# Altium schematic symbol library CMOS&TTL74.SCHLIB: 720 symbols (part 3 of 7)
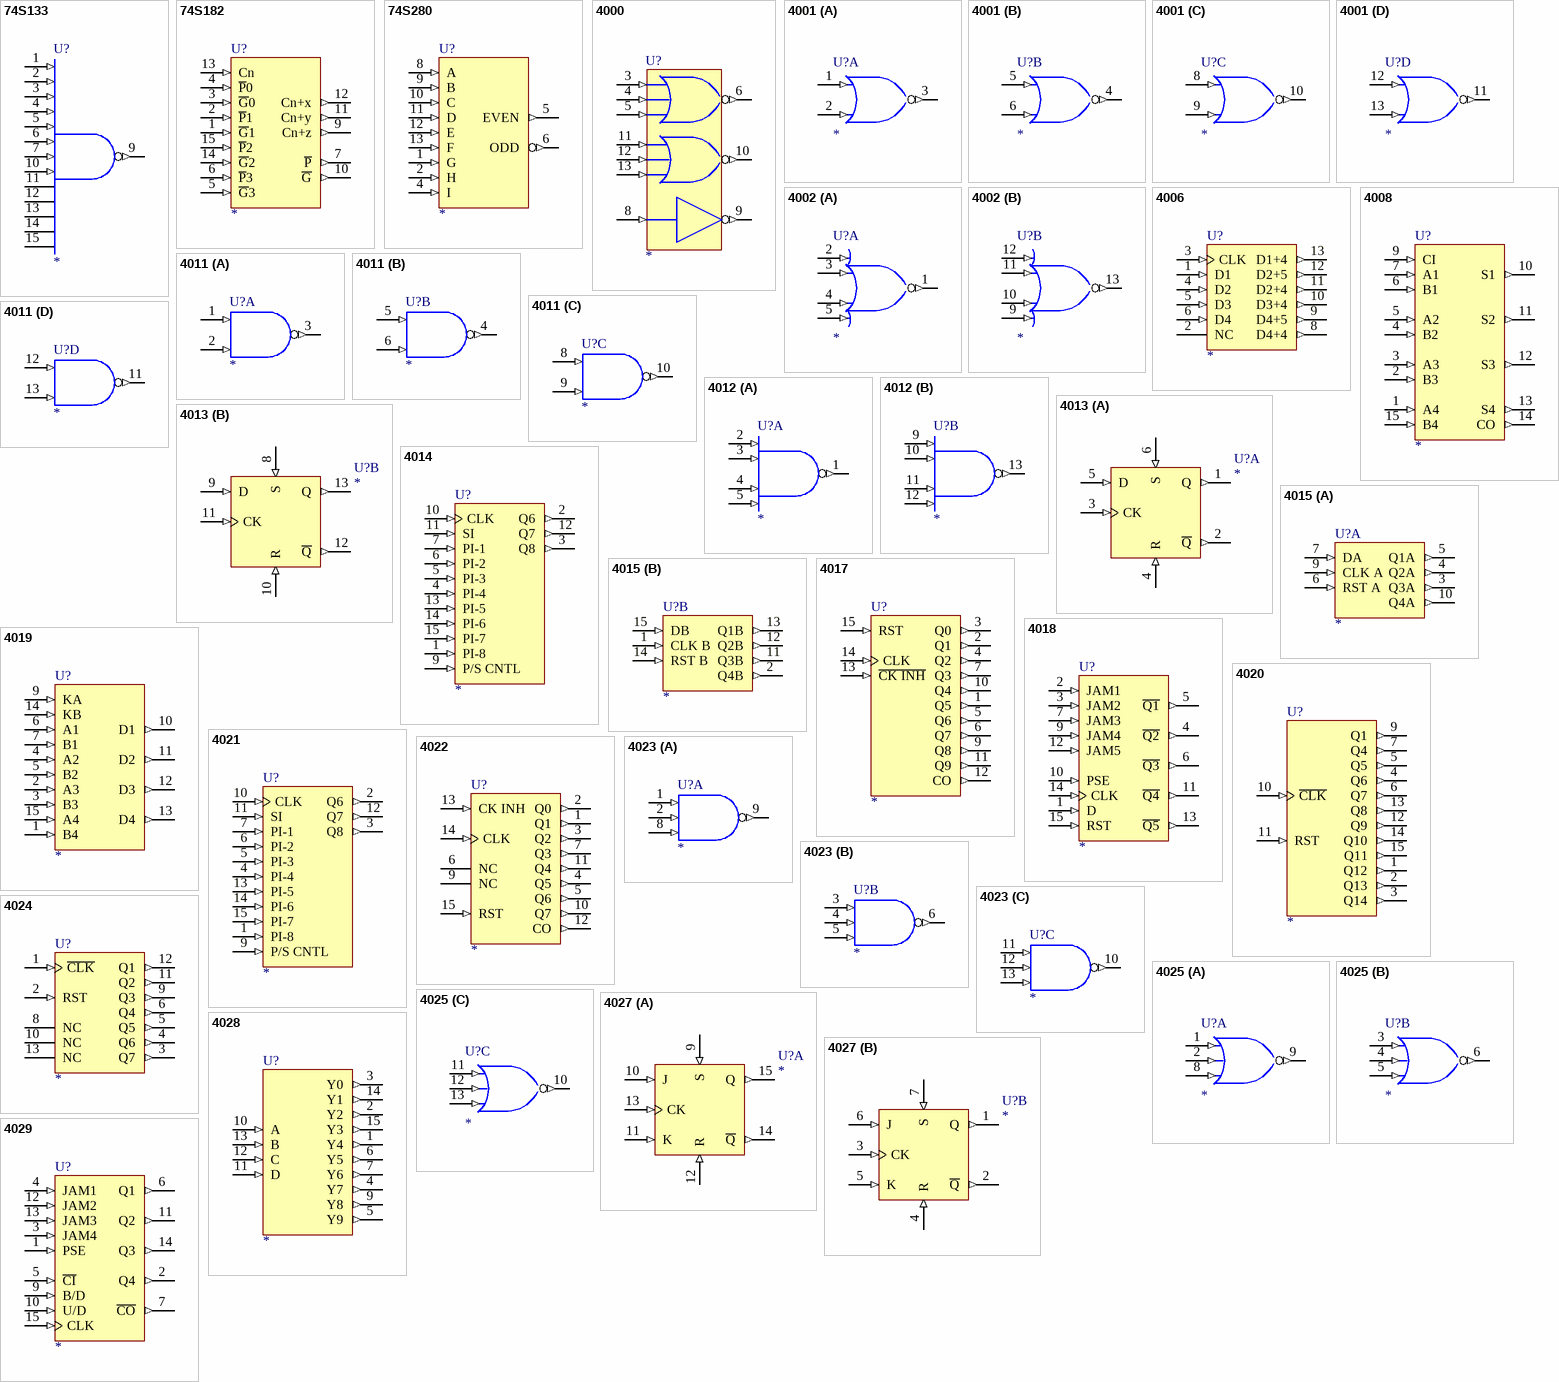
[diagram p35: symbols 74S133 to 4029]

## 4019
designator U?
Quad AND/OR Select Gate
footprint DIP-16
simulation model 4019 (SIMCODE)
pins: 1 B4 (in), 2 A3 (in), 3 B3 (in), 4 A2 (in), 5 B2 (in), 6 A1 (in), 7 B1 (in), 8 GND (power) hidden to GND, 9 KA (in), 10 D1 (out), 11 D2 (out), 12 D3 (out), 13 D4 (out), 14 KB (in), 15 A4 (in), 16 VDD (power) hidden to VDD

## 4020
designator U?
14-Stage Ripple-Carry Binary Counter
footprint DIP-16
simulation model 4020 (SIMCODE)
pins: 1 Q12 (out), 2 Q13 (out), 3 Q14 (out), 4 Q6 (out), 5 Q5 (out), 6 Q7 (out), 7 Q4 (out), 8 GND (power) hidden to GND, 9 Q1 (out), 10 ~{CLK} (in), 11 RST (in), 12 Q9 (out), 13 Q8 (out), 14 Q10 (out), 15 Q11 (out), 16 VDD (power) hidden to VDD
1 alternate drawing of the same symbol

## 4021
designator U?
8-Stage Shift Register (Asynchronous Parallel Input or Synchronous Serial Input/Serial Output)
footprint DIP-16
simulation model 4021 (SIMCODE)
pins: 1 PI-8 (in), 2 Q6 (out), 3 Q8 (out), 4 PI-4 (in), 5 PI-3 (in), 6 PI-2 (in), 7 PI-1 (in), 8 GND (power) hidden to GND, 9 P/S CNTL (in), 10 CLK (in), 11 SI (in), 12 Q7 (out), 13 PI-5 (in), 14 PI-6 (in), 15 PI-7 (in), 16 VDD (power) hidden to VDD

## 4022
designator U?
Octal Counter with 8 Decoded Outputs
footprint DIP-16
simulation model 4022 (SIMCODE)
pins: 1 Q1 (out), 2 Q0 (out), 3 Q2 (out), 4 Q5 (out), 5 Q6 (out), 6 NC, 7 Q3 (out), 8 GND (power) hidden to GND, 9 NC, 10 Q7 (out), 11 Q4 (out), 12 CO (out), 13 CK INH (in), 14 CLK (in), 15 RST (in), 16 VDD (power) hidden to VDD
1 alternate drawing of the same symbol

## 4023
designator U?
Triple 3-Input NAND Gate
footprint DIP-14
simulation model 4023 (SIMCODE)
part A pins: 1 1A (in), 2 1B (in), 7 GND (power) hidden to GND, 8 1C (in), 9 1Y (out), 14 VDD (power) hidden to VDD
part B pins: 3 2A (in), 4 2B (in), 5 2C (in), 6 2Y (out), 7 GND (power) hidden to GND, 14 VDD (power) hidden to VDD
part C pins: 7 GND (power) hidden to GND, 10 3Y (out), 11 3A (in), 12 3B (in), 13 3C (in), 14 VDD (power) hidden to VDD
2 alternate drawings of the same symbol

## 4024
designator U?
7-Stage Ripple-Carry Binary Counter
footprint DIP-14
simulation model 4024 (SIMCODE)
pins: 1 ~{CLK} (in), 2 RST (in), 3 Q7 (out), 4 Q6 (out), 5 Q5 (out), 6 Q4 (out), 7 GND (power) hidden to GND, 8 NC, 9 Q3 (out), 10 NC, 11 Q2 (out), 12 Q1 (out), 13 NC, 14 VDD (power) hidden to VDD
1 alternate drawing of the same symbol

## 4025
designator U?
Triple 3-Input NOR Gate
footprint DIP-14
simulation model 4025 (SIMCODE)
part A pins: 1 A (in), 2 B (in), 7 GND (power) hidden to GND, 8 C (in), 9 J (out), 14 VDD (power) hidden to VDD
part B pins: 3 D (in), 4 E (in), 5 F (in), 6 K (out), 7 GND (power) hidden to GND, 14 VDD (power) hidden to VDD
part C pins: 7 GND (power) hidden to GND, 10 L (out), 11 I (in), 12 H (in), 13 G (in), 14 VDD (power) hidden to VDD
1 alternate drawing of the same symbol

## 4027
designator U?
Dual J-K Master-Slave Flip-Flop
footprint DIP-16
simulation model 4027 (SIMCODE)
part A pins: 8 GND (power) hidden to GND, 9 S (in), 10 J (in), 11 K (in), 12 R (in), 13 CK (in), 14 ~{Q} (out), 15 Q (out), 16 VDD (power) hidden to VDD
part B pins: 1 Q (out), 2 ~{Q} (out), 3 CK (in), 4 R (in), 5 K (in), 6 J (in), 7 S (in), 8 GND (power) hidden to GND, 16 VDD (power) hidden to VDD

## 4028
designator U?
BCD to Decimal Decoder
footprint DIP-16
simulation model 4028 (SIMCODE)
pins: 1 Y4 (out), 2 Y2 (out), 3 Y0 (out), 4 Y7 (out), 5 Y9 (out), 6 Y5 (out), 7 Y6 (out), 8 GND (power) hidden to GND, 9 Y8 (out), 10 A (in), 11 D (in), 12 C (in), 13 B (in), 14 Y1 (out), 15 Y3 (out), 16 VDD (power) hidden to VDD
1 alternate drawing of the same symbol

## 4029
designator U?
Presettable Up/Down Counter Binary or BCD Decade
footprint DIP-16
simulation model 4029 (SIMCODE)
pins: 1 PSE (in), 2 Q4 (out), 3 JAM4 (in), 4 JAM1 (in), 5 ~{CI} (in), 6 Q1 (out), 7 ~{CO} (out), 8 GND (power) hidden to GND, 9 B/D (in), 10 U/D (in), 11 Q2 (out), 12 JAM2 (in), 13 JAM3 (in), 14 Q3 (out), 15 CLK (in), 16 VDD (power) hidden to VDD

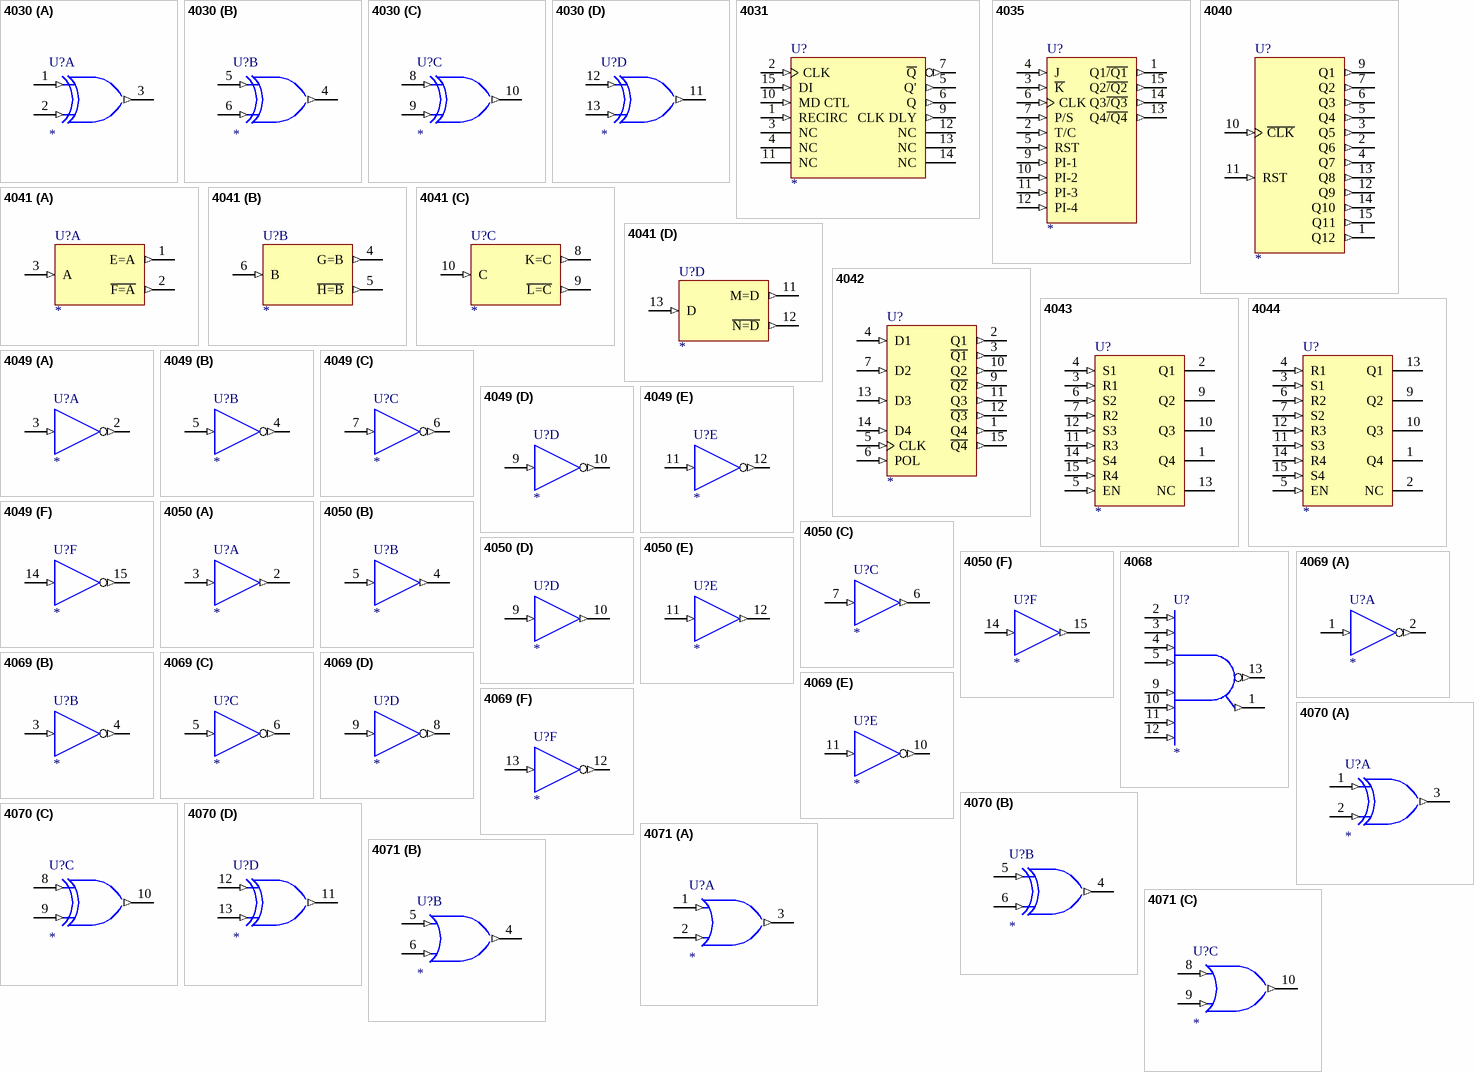
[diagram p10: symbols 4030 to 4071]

## 4030
designator U?
Quad Exclusive-OR Gate
footprint DIP-14
simulation model 4030 (SIMCODE)
part A pins: 1 1A (in), 2 1B (in), 3 1Y (out), 7 GND (power) hidden to GND, 14 VDD (power) hidden to VDD
part B pins: 4 2Y (out), 5 2A (in), 6 2B (in), 7 GND (power) hidden to GND, 14 VDD (power) hidden to VDD
part C pins: 7 GND (power) hidden to GND, 8 3A (in), 9 3B (in), 10 3Y (out), 14 VDD (power) hidden to VDD
part D pins: 7 GND (power) hidden to GND, 11 4Y (out), 12 4A (in), 13 4B (in), 14 VDD (power) hidden to VDD
1 alternate drawing of the same symbol

## 4031
designator U?
64-Stage Static Shift Register
footprint DIP-16
simulation model 4031 (SIMCODE)
pins: 1 RECIRC (in), 2 CLK (in), 3 NC, 4 NC, 5 Q' (out), 6 Q (out), 7 ~{Q} (out), 8 GND (power) hidden to GND, 9 CLK DLY (out), 10 MD CTL (in), 11 NC, 12 NC, 13 NC, 14 NC, 15 DI (in), 16 VDD (power) hidden to VDD

## 4035
designator U?
4-Stage Parallel In/Parallel Out Shift Register
footprint DIP-16
simulation model 4035 (SIMCODE)
pins: 1 Q1~{/Q1} (out), 2 T/C (in), 3 ~{K} (in), 4 J (in), 5 RST (in), 6 CLK (in), 7 P/S (in), 8 GND (power) hidden to GND, 9 PI-1 (in), 10 PI-2 (in), 11 PI-3 (in), 12 PI-4 (in), 13 Q4~{/Q4} (out), 14 Q3~{/Q3} (out), 15 Q2~{/Q2} (out), 16 VDD (power) hidden to VDD

## 4040
designator U?
12-Stage Ripple-Carry Binary Counter
footprint DIP-16
simulation model 4040 (SIMCODE)
pins: 1 Q12 (out), 2 Q6 (out), 3 Q5 (out), 4 Q7 (out), 5 Q4 (out), 6 Q3 (out), 7 Q2 (out), 8 GND (power) hidden to GND, 9 Q1 (out), 10 ~{CLK} (in), 11 RST (in), 12 Q9 (out), 13 Q8 (out), 14 Q10 (out), 15 Q11 (out), 16 VDD (power) hidden to VDD
1 alternate drawing of the same symbol

## 4041
designator U?
Quad True/Complement Buffer
footprint DIP-14
simulation model 4041 (SIMCODE)
part A pins: 1 E=A (out), 2 ~{F=A} (out), 3 A (in), 7 GND (power) hidden to GND, 14 VDD (power) hidden to VDD
part B pins: 4 G=B (out), 5 ~{H=B} (out), 6 B (in), 7 GND (power) hidden to GND, 14 VDD (power) hidden to VDD
part C pins: 7 GND (power) hidden to GND, 8 K=C (out), 9 ~{L=C} (out), 10 C (in), 14 VDD (power) hidden to VDD
part D pins: 7 GND (power) hidden to GND, 11 M=D (out), 12 ~{N=D} (out), 13 D (in), 14 VDD (power) hidden to VDD

## 4042
designator U?
Quad Clocked D-Latch
footprint DIP-16
simulation model 4042 (SIMCODE)
pins: 1 Q4 (out), 2 Q1 (out), 3 ~{Q1} (out), 4 D1 (in), 5 CLK (in), 6 POL (in), 7 D2 (in), 8 GND (power) hidden to GND, 9 ~{Q2} (out), 10 Q2 (out), 11 Q3 (out), 12 ~{Q3} (out), 13 D3 (in), 14 D4 (in), 15 ~{Q4} (out), 16 VDD (power) hidden to VDD

## 4043
designator U?
Quad 3-State R-S Latch
footprint DIP-16
simulation model 4043 (SIMCODE)
pins: 1 Q4 (hiz), 2 Q1 (hiz), 3 R1 (in), 4 S1 (in), 5 EN (in), 6 S2 (in), 7 R2 (in), 8 GND (power) hidden to GND, 9 Q2 (hiz), 10 Q3 (hiz), 11 R3 (in), 12 S3 (in), 13 NC, 14 S4 (in), 15 R4 (in), 16 VDD (power) hidden to VDD

## 4044
designator U?
Quad 3-State R-S Latch
footprint DIP-16
simulation model 4044 (SIMCODE)
pins: 1 Q4 (hiz), 2 NC, 3 S1 (in), 4 R1 (in), 5 EN (in), 6 R2 (in), 7 S2 (in), 8 GND (power) hidden to GND, 9 Q2 (hiz), 10 Q3 (hiz), 11 S3 (in), 12 R3 (in), 13 Q1 (hiz), 14 R4 (in), 15 S4 (in), 16 VDD (power) hidden to VDD

## 4049
designator U?
Inverting Hex Buffer / Converter
footprint DIP-16
simulation model 4049 (SIMCODE)
part A pins: 1 VDD (power) hidden to VDD, 2 1Y (out), 3 1A (in), 8 GND (power) hidden to GND
part B pins: 1 VDD (power) hidden to VDD, 4 2Y (out), 5 2A (in), 8 GND (power) hidden to GND
part C pins: 1 VDD (power) hidden to VDD, 6 3Y (out), 7 3A (in), 8 GND (power) hidden to GND
part D pins: 1 VDD (power) hidden to VDD, 8 GND (power) hidden to GND, 9 4A (in), 10 4Y (out)
part E pins: 1 VDD (power) hidden to VDD, 8 GND (power) hidden to GND, 11 5A (in), 12 5Y (out)
part F pins: 1 VDD (power) hidden to VDD, 8 GND (power) hidden to GND, 14 6A (in), 15 6Y (out)
2 alternate drawings of the same symbol

## 4050
designator U?
Non-Inverting Hex Buffer/Converter
footprint DIP-16
simulation model 4050 (SIMCODE)
part A pins: 1 VDD (power) hidden to VDD, 2 1Y (out), 3 1A (in), 8 GND (power) hidden to GND
part B pins: 1 VDD (power) hidden to VDD, 4 2Y (out), 5 2A (in), 8 GND (power) hidden to GND
part C pins: 1 VDD (power) hidden to VDD, 6 3Y (out), 7 3A (in), 8 GND (power) hidden to GND
part D pins: 1 VDD (power) hidden to VDD, 8 GND (power) hidden to GND, 9 4A (in), 10 4Y (out)
part E pins: 1 VDD (power) hidden to VDD, 8 GND (power) hidden to GND, 11 5A (in), 12 5Y (out)
part F pins: 1 VDD (power) hidden to VDD, 8 GND (power) hidden to GND, 14 6A (in), 15 6Y (out)
1 alternate drawing of the same symbol

## 4068
designator U?
8-Input NAND/AND Gate
footprint DIP-14
simulation model 4068 (SIMCODE)
pins: 1 Y (out), 2 A (in), 3 B (in), 4 C (in), 5 D (in), 7 GND (power) hidden to GND, 9 E (in), 10 F (in), 11 G (in), 12 H (in), 13 ~{Y} (out), 14 VDD (power) hidden to VDD

## 4069
designator U?
Hex Inverter
footprint DIP-14
simulation model 4069 (SIMCODE)
part A pins: 1 A (in), 2 Y (out), 7 GND (power) hidden to GND, 14 VDD (power) hidden to VDD
part B pins: 3 A (in), 4 Y (out), 7 GND (power) hidden to GND, 14 VDD (power) hidden to VDD
part C pins: 5 A (in), 6 Y (out), 7 GND (power) hidden to GND, 14 VDD (power) hidden to VDD
part D pins: 7 GND (power) hidden to GND, 8 Y (out), 9 A (in), 14 VDD (power) hidden to VDD
part E pins: 7 GND (power) hidden to GND, 10 Y (out), 11 A (in), 14 VDD (power) hidden to VDD
part F pins: 7 GND (power) hidden to GND, 12 Y (out), 13 A (in), 14 VDD (power) hidden to VDD

## 4070
designator U?
Quad Exclusive-OR Gate
footprint DIP-14
simulation model 4070 (SIMCODE)
part A pins: 1 1A (in), 2 1B (in), 3 1Y (out), 7 GND (power) hidden to GND, 14 VDD (power) hidden to VDD
part B pins: 4 2Y (out), 5 2A (in), 6 2B (in), 7 GND (power) hidden to GND, 14 VDD (power) hidden to VDD
part C pins: 7 GND (power) hidden to GND, 8 3A (in), 9 3B (in), 10 3Y (out), 14 VDD (power) hidden to VDD
part D pins: 7 GND (power) hidden to GND, 11 4Y (out), 12 4A (in), 13 4B (in), 14 VDD (power) hidden to VDD
1 alternate drawing of the same symbol

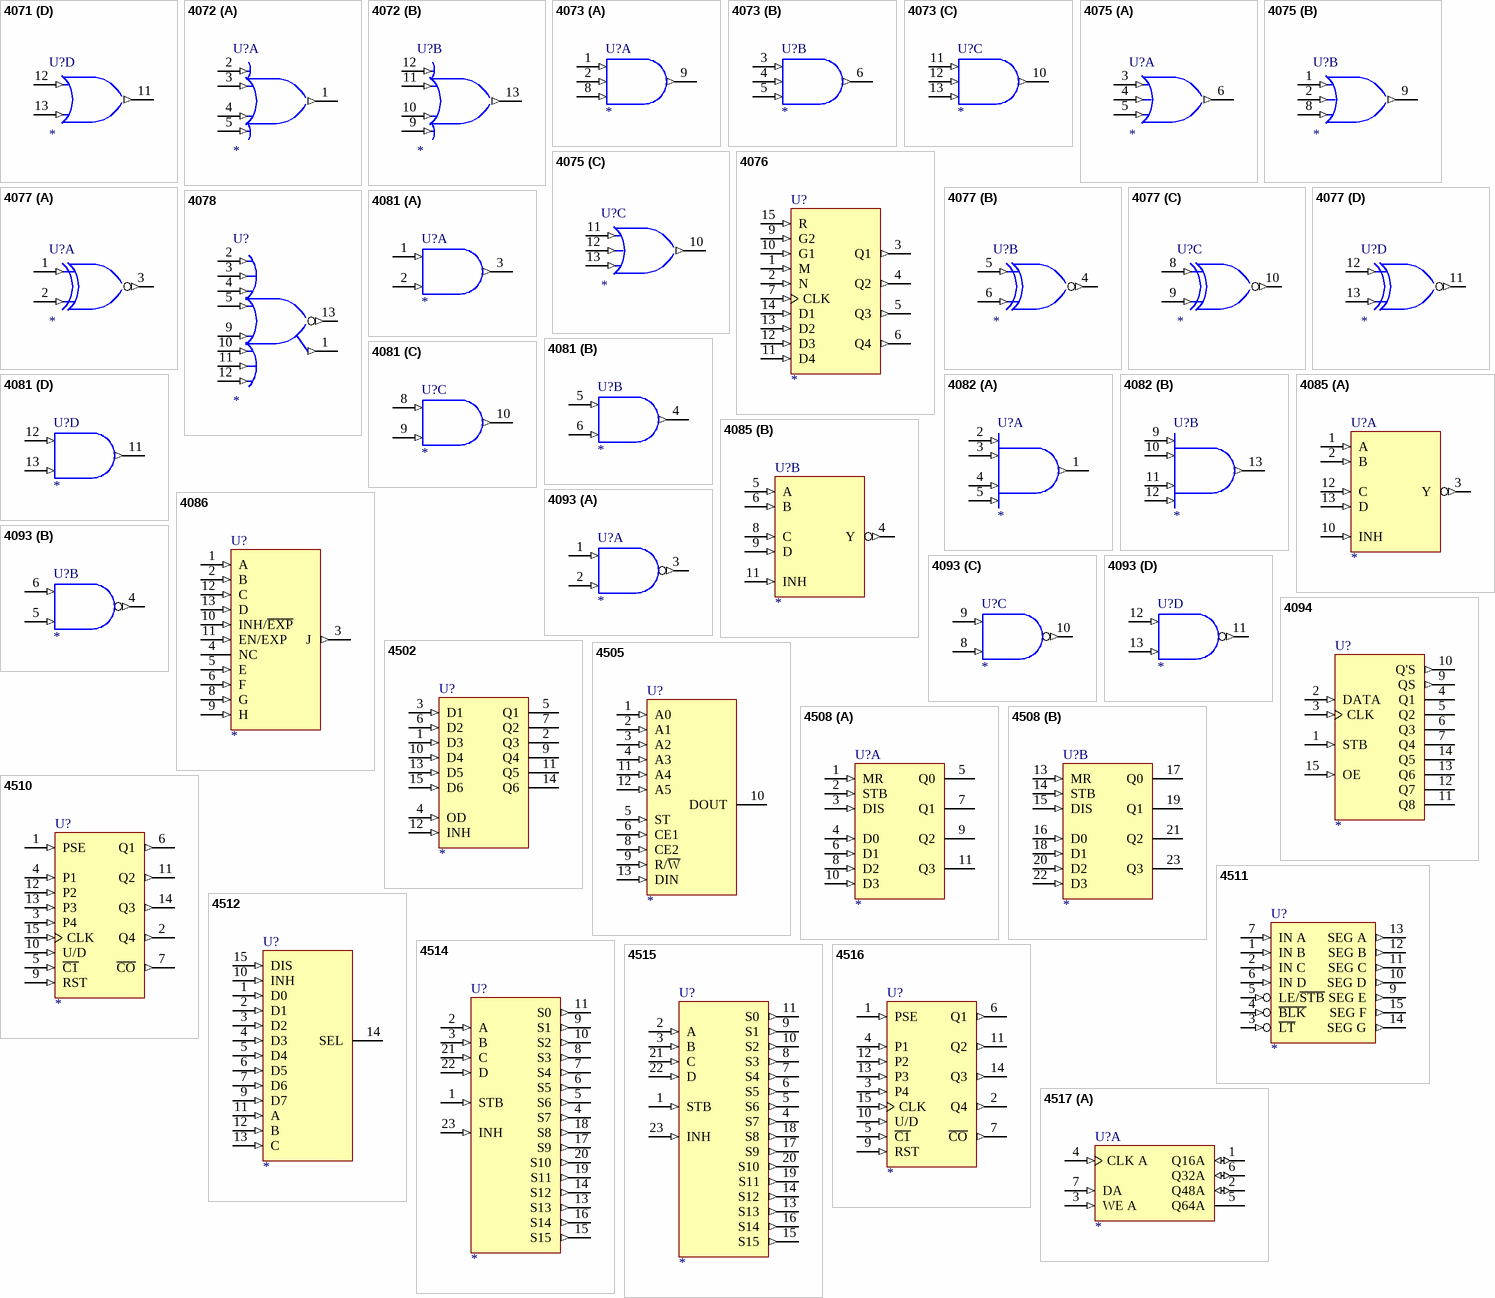
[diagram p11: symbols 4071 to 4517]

## 4071
designator U?
Quad 2-Input OR Gate
footprint DIP-14
simulation model 4071 (SIMCODE)
part A pins: 1 B (in), 2 A (in), 3 J (out), 7 GND (power) hidden to GND, 14 VDD (power) hidden to VDD
part B pins: 4 K (out), 5 D (in), 6 C (in), 7 GND (power) hidden to GND, 14 VDD (power) hidden to VDD
part C pins: 7 GND (power) hidden to GND, 8 F (in), 9 E (in), 10 L (out), 14 VDD (power) hidden to VDD
part D pins: 7 GND (power) hidden to GND, 11 M (out), 12 H (in), 13 G (in), 14 VDD (power) hidden to VDD
1 alternate drawing of the same symbol

## 4072
designator U?
Dual 4-Input OR Gate
footprint DIP-14
simulation model 4072 (SIMCODE)
part A pins: 1 1Y (out), 2 1A (in), 3 1B (in), 4 1C (in), 5 1D (in), 7 GND (power) hidden to GND, 14 VDD (power) hidden to VDD
part B pins: 7 GND (power) hidden to GND, 9 2D (in), 10 2C (in), 11 2B (in), 12 2A (in), 13 2Y (out), 14 VDD (power) hidden to VDD
2 alternate drawings of the same symbol

## 4073
designator U?
Triple 3-Input AND Gate
footprint DIP-14
simulation model 4073 (SIMCODE)
part A pins: 1 1A (in), 2 1B (in), 7 GND (power) hidden to GND, 8 1C (in), 9 1Y (out), 14 VDD (power) hidden to VDD
part B pins: 3 2A (in), 4 2B (in), 5 2C (in), 6 2Y (out), 7 GND (power) hidden to GND, 14 VDD (power) hidden to VDD
part C pins: 7 GND (power) hidden to GND, 10 3Y (out), 11 3A (in), 12 3B (in), 13 3C (in), 14 VDD (power) hidden to VDD
2 alternate drawings of the same symbol

## 4075
designator U?
Triple 3-Input OR Gate
footprint DIP-14
simulation model 4075 (SIMCODE)
part A pins: 3 1A (in), 4 1B (in), 5 1C (in), 6 1Y (out), 7 GND (power) hidden to GND, 14 VDD (power) hidden to VDD
part B pins: 1 2A (in), 2 2B (in), 7 GND (power) hidden to GND, 8 2C (in), 9 2Y (out), 14 VDD (power) hidden to VDD
part C pins: 7 GND (power) hidden to GND, 10 3Y (out), 11 3A (in), 12 3B (in), 13 3C (in), 14 VDD (power) hidden to VDD
2 alternate drawings of the same symbol

## 4076
designator U?
4-Bit D-Type Register
footprint DIP-16
simulation model 4076 (SIMCODE)
pins: 1 M (in), 2 N (in), 3 Q1 (out), 4 Q2 (out), 5 Q3 (out), 6 Q4 (out), 7 CLK (in), 8 GND (power) hidden to GND, 9 G2 (in), 10 G1 (in), 11 D4 (in), 12 D3 (in), 13 D2 (in), 14 D1 (in), 15 R (in), 16 VDD (power) hidden to VDD
1 alternate drawing of the same symbol

## 4077
designator U?
Quad Exclusive-NOR Gate
footprint DIP-14
simulation model 4077 (SIMCODE)
part A pins: 1 1A (in), 2 1B (in), 3 1Y (out), 7 GND (power) hidden to GND, 14 VDD (power) hidden to VDD
part B pins: 4 2Y (out), 5 2A (in), 6 2B (in), 7 GND (power) hidden to GND, 14 VDD (power) hidden to VDD
part C pins: 7 GND (power) hidden to GND, 8 3A (in), 9 3B (in), 10 3Y (out), 14 VDD (power) hidden to VDD
part D pins: 7 GND (power) hidden to GND, 11 4Y (out), 12 4A (in), 13 4B (in), 14 VDD (power) hidden to VDD
1 alternate drawing of the same symbol

## 4078
designator U?
8-Input NOR/OR Gate
footprint DIP-14
simulation model 4078 (SIMCODE)
pins: 1 X (out), 2 A (in), 3 B (in), 4 C (in), 5 D (in), 7 GND (power) hidden to GND, 9 E (in), 10 F (in), 11 G (in), 12 H (in), 13 ~{X} (out), 14 VDD (power) hidden to VDD
1 alternate drawing of the same symbol

## 4081
designator U?
Quad 2-Input AND Gate
footprint DIP-14
simulation model 4081 (SIMCODE)
part A pins: 1 1A (in), 2 1B (in), 3 1Y (out), 7 GND (power) hidden to GND, 14 VDD (power) hidden to VDD
part B pins: 4 2Y (out), 5 2A (in), 6 2B (in), 7 GND (power) hidden to GND, 14 VDD (power) hidden to VDD
part C pins: 7 GND (power) hidden to GND, 8 3A (in), 9 3B (in), 10 3Y (out), 14 VDD (power) hidden to VDD
part D pins: 7 GND (power) hidden to GND, 11 4Y (out), 12 4A (in), 13 4B (in), 14 VDD (power) hidden to VDD
2 alternate drawings of the same symbol

## 4082
designator U?
Dual 4-Input AND Gate
footprint DIP-14
simulation model 4082 (SIMCODE)
part A pins: 1 Y (out), 2 A (in), 3 B (in), 4 C (in), 5 D (in), 7 GND (power) hidden to GND, 14 VDD (power) hidden to VDD
part B pins: 7 GND (power) hidden to GND, 9 A (in), 10 B (in), 11 C (in), 12 D (in), 13 Y (out), 14 VDD (power) hidden to VDD
2 alternate drawings of the same symbol

## 4085
designator U?
Dual 2-Wide 2-Input AND-OR-Inverter Gate
footprint DIP-14
simulation model 4085 (SIMCODE)
part A pins: 1 A (in), 2 B (in), 3 Y (out), 7 GND (power) hidden to GND, 10 INH (in), 12 C (in), 13 D (in), 14 VDD (power) hidden to VDD
part B pins: 4 Y (out), 5 A (in), 6 B (in), 7 GND (power) hidden to GND, 8 C (in), 9 D (in), 11 INH (in), 14 VDD (power) hidden to VDD

## 4086
designator U?
Expandable 4-Wide 2-Input AND-OR-INVERT Gate
footprint DIP-14
simulation model 4086 (SIMCODE)
pins: 1 A (in), 2 B (in), 3 J (out), 4 NC, 5 E (in), 6 F (in), 7 GND (power) hidden to GND, 8 G (in), 9 H (in), 10 INH/~{EXP} (in), 11 EN/EXP (in), 12 C (in), 13 D (in), 14 VDD (power) hidden to VDD

## 4093
designator U?
Quad 2-Input NAND Schmitt-Trigger
footprint DIP-14
simulation model 4093 (SIMCODE)
part A pins: 1 1A (in), 2 1B (in), 3 1Y (out), 7 GND (power) hidden to GND, 14 VDD (power) hidden to VDD
part B pins: 4 2Y (out), 5 2B (in), 6 2A (in), 7 GND (power) hidden to GND, 14 VDD (power) hidden to VDD
part C pins: 7 GND (power) hidden to GND, 8 3B (in), 9 3A (in), 10 3Y (out), 14 VDD (power) hidden to VDD
part D pins: 7 GND (power) hidden to GND, 11 4Y (out), 12 4A (in), 13 4B (in), 14 VDD (power) hidden to VDD
1 alternate drawing of the same symbol

## 4094
designator U?
8-Stage Shift-and-Store Bus Register
footprint DIP-16
simulation model 4094 (SIMCODE)
pins: 1 STB (in), 2 DATA (in), 3 CLK (in), 4 Q1 (hiz), 5 Q2 (hiz), 6 Q3 (hiz), 7 Q4 (hiz), 8 GND (power) hidden to GND, 9 QS (out), 10 Q'S (out), 11 Q8 (hiz), 12 Q7 (hiz), 13 Q6 (hiz), 14 Q5 (hiz), 15 OE (in), 16 VDD (power) hidden to VDD

## 4502
designator U?
Strobed Hex Inverter/Buffer
footprint DIP-16
simulation model 4502 (SIMCODE)
pins: 1 D3 (in), 2 Q3 (hiz), 3 D1 (in), 4 OD (in), 5 Q1 (hiz), 6 D2 (in), 7 Q2 (hiz), 8 GND (power) hidden to GND, 9 Q4 (hiz), 10 D4 (in), 11 Q5 (hiz), 12 INH (in), 13 D5 (in), 14 Q6 (hiz), 15 D6 (in), 16 VDD (power) hidden to VDD

## 4505
designator U?
64-Bit, 1-Bit per word Random Access Read/Write Memory
footprint DIP-14
simulation model 4505 (SIMCODE)
pins: 1 A0 (in), 2 A1 (in), 3 A2 (in), 4 A3 (in), 5 ST (in), 6 CE1 (in), 7 GND (power) hidden to GND, 8 CE2 (in), 9 R/~{W} (in), 10 DOUT (hiz), 11 A4 (in), 12 A5 (in), 13 DIN (in), 14 VDD (power) hidden to VDD

## 4508
designator U?
Dual 4-Bit Latch with 3-State Outputs
footprint DIP-24
simulation model 4508 (SIMCODE)
part A pins: 1 MR (in), 2 STB (in), 3 DIS (in), 4 D0 (in), 5 Q0 (hiz), 6 D1 (in), 7 Q1 (hiz), 8 D2 (in), 9 Q2 (hiz), 10 D3 (in), 11 Q3 (hiz), 12 GND (power) hidden to GND, 24 VDD (power) hidden to VDD
part B pins: 12 GND (power) hidden to GND, 13 MR (in), 14 STB (in), 15 DIS (in), 16 D0 (in), 17 Q0 (hiz), 18 D1 (in), 19 Q1 (hiz), 20 D2 (in), 21 Q2 (hiz), 22 D3 (in), 23 Q3 (hiz), 24 VDD (power) hidden to VDD

## 4510
designator U?
Presettable Up/Down Counter
footprint DIP-16
simulation model 4510 (SIMCODE)
pins: 1 PSE (in), 2 Q4 (out), 3 P4 (in), 4 P1 (in), 5 ~{C1} (in), 6 Q1 (out), 7 ~{CO} (out), 8 GND (power) hidden to GND, 9 RST (in), 10 U/D (in), 11 Q2 (out), 12 P2 (in), 13 P3 (in), 14 Q3 (out), 15 CLK (in), 16 VDD (power) hidden to VDD

## 4511
designator U?
BCD-TO-7 Segment Latch/Decoder/LCD Driver
footprint DIP-16
simulation model 4511 (SIMCODE)
pins: 1 IN B (in), 2 IN C (in), 3 ~{LT} (in), 4 ~{BLK} (in), 5 LE/~{STB} (in), 6 IN D (in), 7 IN A (in), 8 GND (power) hidden to GND, 9 SEG E (out), 10 SEG D (out), 11 SEG C (out), 12 SEG B (out), 13 SEG A (out), 14 SEG G (out), 15 SEG F (out), 16 VDD (power) hidden to VDD

## 4512
designator U?
8-Channel Data Selector
footprint DIP-16
simulation model 4512 (SIMCODE)
pins: 1 D0 (in), 2 D1 (in), 3 D2 (in), 4 D3 (in), 5 D4 (in), 6 D5 (in), 7 D6 (in), 8 GND (power) hidden to GND, 9 D7 (in), 10 INH (in), 11 A (in), 12 B (in), 13 C (in), 14 SEL (hiz), 15 DIS (in), 16 VDD (power) hidden to VDD

## 4514
designator U?
4-Bit Latch/4-to-16 Line Decoder
footprint DIP-24
simulation model 4514 (SIMCODE)
pins: 1 STB (in), 2 A (in), 3 B (in), 4 S7 (out), 5 S6 (out), 6 S5 (out), 7 S4 (out), 8 S3 (out), 9 S1 (out), 10 S2 (out), 11 S0 (out), 12 GND (power) hidden to GND, 13 S13 (out), 14 S12 (out), 15 S15 (out), 16 S14 (out), 17 S9 (out), 18 S8 (out), 19 S11 (out), 20 S10 (out), 21 C (in), 22 D (in), 23 INH (in), 24 VDD (power) hidden to VDD
1 alternate drawing of the same symbol

## 4515
designator U?
4-Bit Latch/4-to-16 Line Decoder
footprint DIP-24
simulation model 4515 (SIMCODE)
pins: 1 STB (in), 2 A (in), 3 B (in), 4 S7 (out), 5 S6 (out), 6 S5 (out), 7 S4 (out), 8 S3 (out), 9 S1 (out), 10 S2 (out), 11 S0 (out), 12 GND (power) hidden to GND, 13 S13 (out), 14 S12 (out), 15 S15 (out), 16 S14 (out), 17 S9 (out), 18 S8 (out), 19 S11 (out), 20 S10 (out), 21 C (in), 22 D (in), 23 INH (in), 24 VDD (power) hidden to VDD
1 alternate drawing of the same symbol

## 4516
designator U?
Presettable Up/Down Counter
footprint DIP-16
simulation model 4516 (SIMCODE)
pins: 1 PSE (in), 2 Q4 (out), 3 P4 (in), 4 P1 (in), 5 ~{C1} (in), 6 Q1 (out), 7 ~{CO} (out), 8 GND (power) hidden to GND, 9 RST (in), 10 U/D (in), 11 Q2 (out), 12 P2 (in), 13 P3 (in), 14 Q3 (out), 15 CLK (in), 16 VDD (power) hidden to VDD

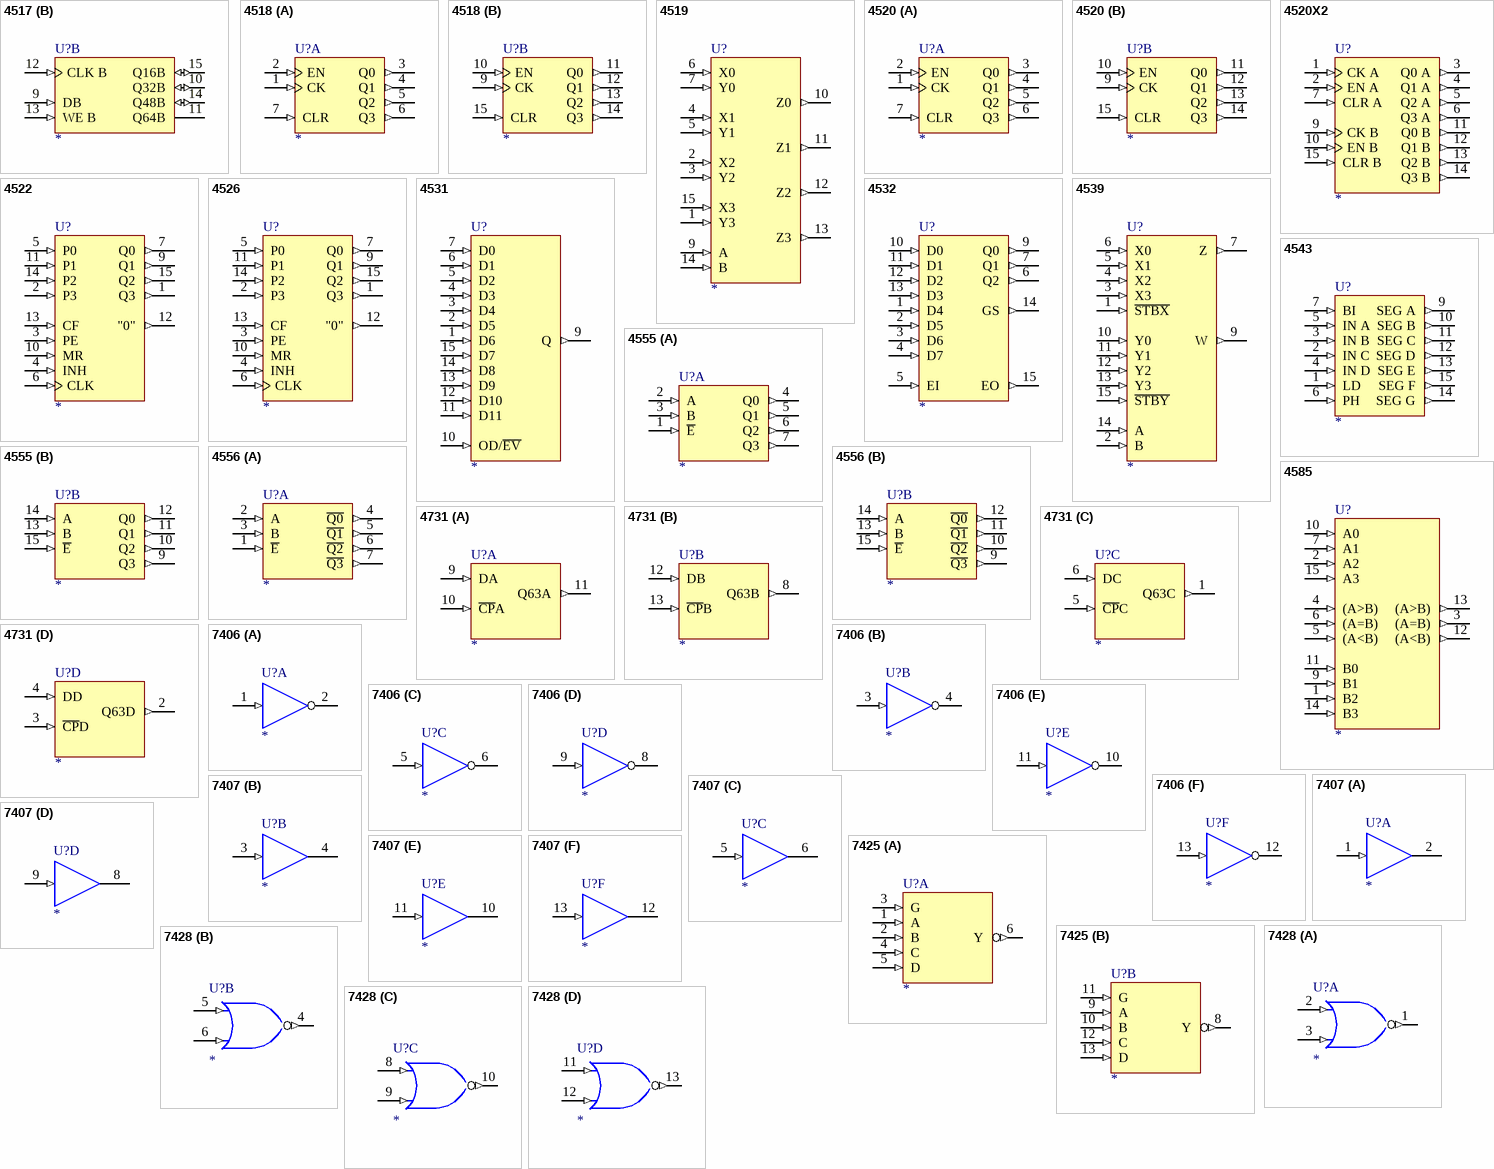
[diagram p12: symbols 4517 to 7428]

## 4517
designator U?
Dual 64-Stage Static Shift Register
footprint DIP-16
simulation model 4517 (SIMCODE)
part A pins: 1 Q16A (io), 2 Q48A (io), 3 WE A (in), 4 CLK A (in), 5 Q64A (hiz), 6 Q32A (io), 7 DA (in), 8 GND (power) hidden to GND, 16 VDD (power) hidden to VDD
part B pins: 8 GND (power) hidden to GND, 9 DB (in), 10 Q32B (io), 11 Q64B (hiz), 12 CLK B (in), 13 WE B (in), 14 Q48B (io), 15 Q16B (io), 16 VDD (power) hidden to VDD

## 4518
designator U?
Dual BCD Up - Counter
footprint DIP-16
simulation model 4518 (SIMCODE)
part A pins: 1 CK (in), 2 EN (in), 3 Q0 (out), 4 Q1 (out), 5 Q2 (out), 6 Q3 (out), 7 CLR (in), 8 GND (power) hidden to GND, 16 VDD (power) hidden to VDD
part B pins: 8 GND (power) hidden to GND, 9 CK (in), 10 EN (in), 11 Q0 (out), 12 Q1 (out), 13 Q2 (out), 14 Q3 (out), 15 CLR (in), 16 VDD (power) hidden to VDD
1 alternate drawing of the same symbol

## 4519
designator U?
Quad 2-Input Multiplexer
footprint DIP-16
simulation model 4519 (SIMCODE)
pins: 1 Y3 (in), 2 X2 (in), 3 Y2 (in), 4 X1 (in), 5 Y1 (in), 6 X0 (in), 7 Y0 (in), 8 GND (power) hidden to GND, 9 A (in), 10 Z0 (out), 11 Z1 (out), 12 Z2 (out), 13 Z3 (out), 14 B (in), 15 X3 (in), 16 VDD (power) hidden to VDD

## 4520
designator U?
Dual Binary Up - Counter
footprint DIP-16
simulation model 4520 (SIMCODE)
part A pins: 1 CK (in), 2 EN (in), 3 Q0 (out), 4 Q1 (out), 5 Q2 (out), 6 Q3 (out), 7 CLR (in), 8 GND (power) hidden to GND, 16 VDD (power) hidden to VDD
part B pins: 8 GND (power) hidden to GND, 9 CK (in), 10 EN (in), 11 Q0 (out), 12 Q1 (out), 13 Q2 (out), 14 Q3 (out), 15 CLR (in), 16 VDD (power) hidden to VDD
1 alternate drawing of the same symbol

## 4520X2
designator U?
Dual Binary Up - Counter
footprint DIP-16
simulation model 4520X2 (SIMCODE)
pins: 1 CK A (in), 2 EN A (in), 3 Q0 A (out), 4 Q1 A (out), 5 Q2 A (out), 6 Q3 A (out), 7 CLR A (in), 8 GND (power) hidden to GND, 9 CK B (in), 10 EN B (in), 11 Q0 B (out), 12 Q1 B (out), 13 Q2 B (out), 14 Q3 B (out), 15 CLR B (in), 16 VDD (power) hidden to VDD
1 alternate drawing of the same symbol

## 4522
designator U?
Programmable 4-Bit BCD Down Counter
footprint DIP-16
simulation model 4522 (SIMCODE)
pins: 1 Q3 (out), 2 P3 (in), 3 PE (in), 4 INH (in), 5 P0 (in), 6 CLK (in), 7 Q0 (out), 8 GND (power) hidden to GND, 9 Q1 (out), 10 MR (in), 11 P1 (in), 12 "0" (out), 13 CF (in), 14 P2 (in), 15 Q2 (out), 16 VDD (power) hidden to VDD

## 4526
designator U?
Programmable 4-Bit Binary Down Counter
footprint DIP-16
simulation model 4526 (SIMCODE)
pins: 1 Q3 (out), 2 P3 (in), 3 PE (in), 4 INH (in), 5 P0 (in), 6 CLK (in), 7 Q0 (out), 8 GND (power) hidden to GND, 9 Q1 (out), 10 MR (in), 11 P1 (in), 12 "0" (out), 13 CF (in), 14 P2 (in), 15 Q2 (out), 16 VDD (power) hidden to VDD

## 4531
designator U?
12-Input Parity Generator
footprint DIP-16
simulation model 4531 (SIMCODE)
pins: 1 D6 (in), 2 D5 (in), 3 D4 (in), 4 D3 (in), 5 D2 (in), 6 D1 (in), 7 D0 (in), 8 GND (power) hidden to GND, 9 Q (out), 10 OD/~{EV} (in), 11 D11 (in), 12 D10 (in), 13 D9 (in), 14 D8 (in), 15 D7 (in), 16 VDD (power) hidden to VDD

## 4532
designator U?
Priority Encoder (8-Level)
footprint DIP-16
simulation model 4532 (SIMCODE)
pins: 1 D4 (in), 2 D5 (in), 3 D6 (in), 4 D7 (in), 5 EI (in), 6 Q2 (out), 7 Q1 (out), 8 GND (power) hidden to GND, 9 Q0 (out), 10 D0 (in), 11 D1 (in), 12 D2 (in), 13 D3 (in), 14 GS (out), 15 EO (out), 16 VDD (power) hidden to VDD

## 4539
designator U?
Dual 4-Input Data Selector
footprint DIP-16
simulation model 4539 (SIMCODE)
pins: 1 ~{STBX} (in), 2 B (in), 3 X3 (in), 4 X2 (in), 5 X1 (in), 6 X0 (in), 7 Z (out), 8 GND (power) hidden to GND, 9 W (out), 10 Y0 (in), 11 Y1 (in), 12 Y2 (in), 13 Y3 (in), 14 A (in), 15 ~{STBY} (in), 16 VDD (power) hidden to VDD

## 4543
designator U?
BCD-to-7 Segment Latch/Decoder/LCD Driver
footprint DIP-16
simulation model 4543 (SIMCODE)
pins: 1 LD (in), 2 IN C (in), 3 IN B (in), 4 IN D (in), 5 IN A (in), 6 PH (in), 7 BI (in), 8 GND (power) hidden to GND, 9 SEG A (out), 10 SEG B (out), 11 SEG C (out), 12 SEG D (out), 13 SEG E (out), 14 SEG G (out), 15 SEG F (out), 16 VDD (power) hidden to VDD

## 4555
designator U?
Dual Binary to 1-of-4 Decoder/Demultiplexer
footprint DIP-16
simulation model 4555 (SIMCODE)
part A pins: 1 ~{E} (in), 2 A (in), 3 B (in), 4 Q0 (out), 5 Q1 (out), 6 Q2 (out), 7 Q3 (out), 8 GND (power) hidden to GND, 16 VDD (power) hidden to VDD
part B pins: 8 GND (power) hidden to GND, 9 Q3 (out), 10 Q2 (out), 11 Q1 (out), 12 Q0 (out), 13 B (in), 14 A (in), 15 ~{E} (in), 16 VDD (power) hidden to VDD

## 4556
designator U?
Dual Binary to 1-of-4 Decoder/Demultiplexer (Inverting)
footprint DIP-16
simulation model 4556 (SIMCODE)
part A pins: 1 ~{E} (in), 2 A (in), 3 B (in), 4 ~{Q0} (out), 5 ~{Q1} (out), 6 ~{Q2} (out), 7 ~{Q3} (out), 8 GND (power) hidden to GND, 16 VDD (power) hidden to VDD
part B pins: 8 GND (power) hidden to GND, 9 ~{Q3} (out), 10 ~{Q2} (out), 11 ~{Q1} (out), 12 ~{Q0} (out), 13 B (in), 14 A (in), 15 ~{E} (in), 16 VDD (power) hidden to VDD

## 4585
designator U?
4-Bit Magnitude Comparator
footprint DIP-16
simulation model 4585 (SIMCODE)
pins: 1 B2 (in), 2 A2 (in), 3 (A=B) (out), 4 (A>B)  (in), 5 (A<B)  (in), 6 (A=B)  (in), 7 A1 (in), 8 GND (power) hidden to GND, 9 B1 (in), 10 A0 (in), 11 B0 (in), 12 (A<B) (out), 13 (A>B) (out), 14 B3  (in), 15 A3  (in), 16 VDD (power) hidden to VDD

## 4731
designator U?
Quad 64-Bit Static Shift Register
footprint DIP-14
simulation model 4731 (SIMCODE)
part A pins: 7 GND (power) hidden to GND, 9 DA (in), 10 ~{CP}A (in), 11 Q63A (out), 14 VDD (power) hidden to VDD
part B pins: 7 GND (power) hidden to GND, 8 Q63B (out), 12 DB (in), 13 ~{CP}B (in), 14 VDD (power) hidden to VDD
part C pins: 1 Q63C (out), 5 ~{CP}C (in), 6 DC (in), 7 GND (power) hidden to GND, 14 VDD (power) hidden to VDD
part D pins: 2 Q63D (out), 3 ~{CP}D (in), 4 DD (in), 7 GND (power) hidden to GND, 14 VDD (power) hidden to VDD

## 7406
designator U?
Hex Inverter with Open-Collector High-Voltage Output
footprint DIP-14
simulation model 7406 (SIMCODE)
part A pins: 1 A (in), 2 Y (oc), 7 GND (power) hidden to GND, 14 VCC (power) hidden to VCC
part B pins: 3 A (in), 4 Y (oc), 7 GND (power) hidden to GND, 14 VCC (power) hidden to VCC
part C pins: 5 A (in), 6 Y (oc), 7 GND (power) hidden to GND, 14 VCC (power) hidden to VCC
part D pins: 7 GND (power) hidden to GND, 8 Y (oc), 9 A (in), 14 VCC (power) hidden to VCC
part E pins: 7 GND (power) hidden to GND, 10 Y (oc), 11 A (in), 14 VCC (power) hidden to VCC
part F pins: 7 GND (power) hidden to GND, 12 Y (oc), 13 A (in), 14 VCC (power) hidden to VCC
2 alternate drawings of the same symbol

## 7407
designator U?
Hex Buffer/Driver with Open-Collector High-Voltage Output
footprint DIP-14
simulation model 7407 (SIMCODE)
part A pins: 1 A (in), 2 Y (oc), 7 GND (power) hidden to GND, 14 VCC (power) hidden to VCC
part B pins: 3 A (in), 4 Y (oc), 7 GND (power) hidden to GND, 14 VCC (power) hidden to VCC
part C pins: 5 A (in), 6 Y (oc), 7 GND (power) hidden to GND, 14 VCC (power) hidden to VCC
part D pins: 7 GND (power) hidden to GND, 8 Y (oc), 9 A (in), 14 VCC (power) hidden to VCC
part E pins: 7 GND (power) hidden to GND, 10 Y (oc), 11 A (in), 14 VCC (power) hidden to VCC
part F pins: 7 GND (power) hidden to GND, 12 Y (oc), 13 A (in), 14 VCC (power) hidden to VCC
2 alternate drawings of the same symbol

## 7425
designator U?
Dual 4-Input NOR Gate with Strobe
footprint DIP-14
simulation model 7425 (SIMCODE)
part A pins: 1 A (in), 2 B (in), 3 G (in), 4 C (in), 5 D (in), 6 Y (out), 7 GND (power) hidden to GND, 14 VCC (power) hidden to VCC
part B pins: 7 GND (power) hidden to GND, 8 Y (out), 9 A (in), 10 B (in), 11 G (in), 12 C (in), 13 D (in), 14 VCC (power) hidden to VCC
1 alternate drawing of the same symbol

## 7428
designator U?
Quad 2-Input NOR Gate
footprint DIP-14
simulation model 7428 (SIMCODE)
part A pins: 1 Y (out), 2 A (in), 3 B (in), 7 GND (power) hidden to GND, 14 VCC (power) hidden to VCC
part B pins: 4 Y (out), 5 A (in), 6 B (in), 7 GND (power) hidden to GND, 14 VCC (power) hidden to VCC
part C pins: 7 GND (power) hidden to GND, 8 A (in), 9 B (in), 10 Y (out), 14 VCC (power) hidden to VCC
part D pins: 7 GND (power) hidden to GND, 11 A (in), 12 B (in), 13 Y (out), 14 VCC (power) hidden to VCC
1 alternate drawing of the same symbol

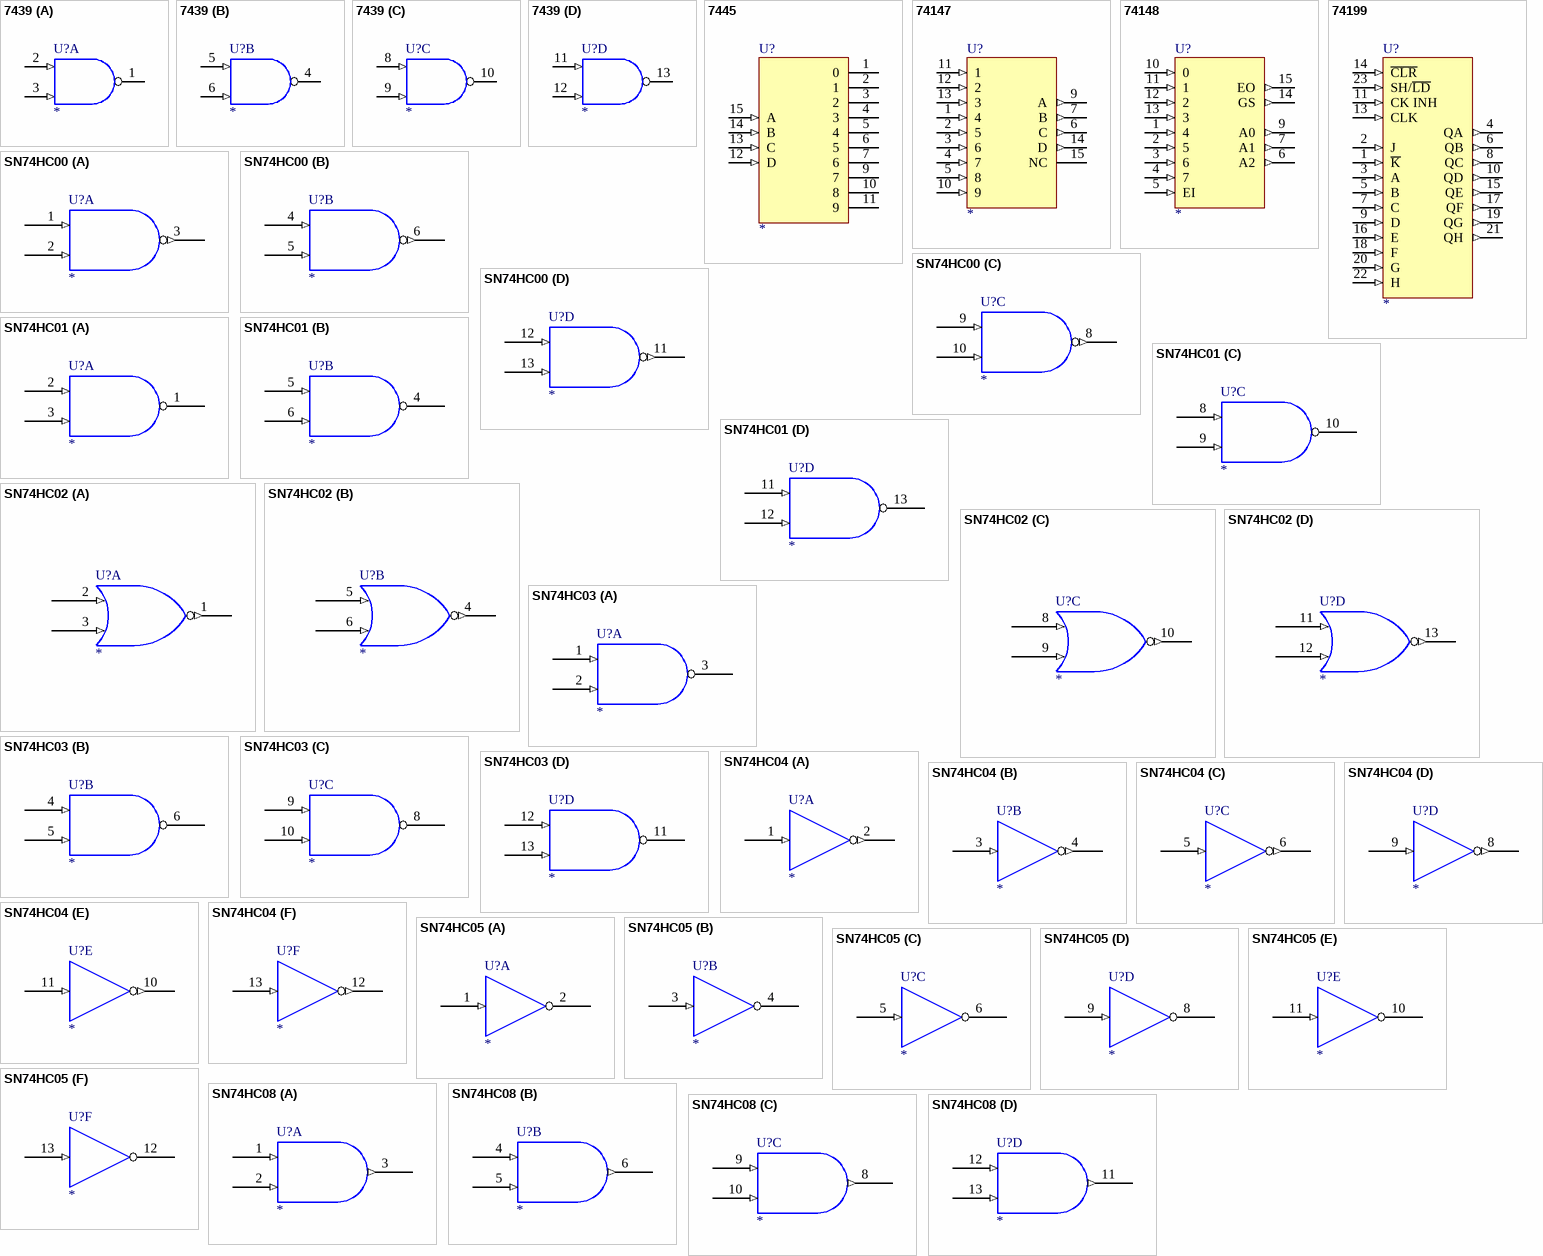
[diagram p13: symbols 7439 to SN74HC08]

## 7439
designator U?
Quad 2-Input Positive-NAND Buffer with Open-Collector Output
footprint DIP-14
simulation model 7439 (SIMCODE)
part A pins: 1 Y (oc), 2 A (in), 3 B (in), 7 GND (power) hidden to GND, 14 VCC (power) hidden to VCC
part B pins: 4 Y (oc), 5 A (in), 6 B (in), 7 GND (power) hidden to GND, 14 VCC (power) hidden to VCC
part C pins: 7 GND (power) hidden to GND, 8 A (in), 9 B (in), 10 Y (oc), 14 VCC (power) hidden to VCC
part D pins: 7 GND (power) hidden to GND, 11 A (in), 12 B (in), 13 Y (oc), 14 VCC (power) hidden to VCC
1 alternate drawing of the same symbol

## 7445
designator U?
BCD-to-Decimal Decoder/Driver
footprint DIP-16
simulation model 7445 (SIMCODE)
pins: 1 0 (oc), 2 1 (oc), 3 2 (oc), 4 3 (oc), 5 4 (oc), 6 5 (oc), 7 6 (oc), 8 GND (power) hidden to GND, 9 7 (oc), 10 8 (oc), 11 9 (oc), 12 D (in), 13 C (in), 14 B (in), 15 A (in), 16 VCC (power) hidden to VCC
1 alternate drawing of the same symbol

## 74147
designator U?
10-Line to 4-Line Priority Encoder
footprint DIP-16
simulation model 74147 (SIMCODE)
pins: 1 4 (in), 2 5 (in), 3 6 (in), 4 7 (in), 5 8 (in), 6 C (out), 7 B (out), 8 GND (power) hidden to GND, 9 A (out), 10 9 (in), 11 1 (in), 12 2 (in), 13 3 (in), 14 D (out), 15 NC, 16 VCC (power) hidden to VCC
1 alternate drawing of the same symbol

## 74148
designator U?
8-Line to 3-Line Priority Encoder
footprint DIP-16
simulation model 74148 (SIMCODE)
pins: 1 4 (in), 2 5 (in), 3 6 (in), 4 7 (in), 5 EI (in), 6 A2 (out), 7 A1 (out), 8 GND (power) hidden to GND, 9 A0 (out), 10 0 (in), 11 1 (in), 12 2 (in), 13 3 (in), 14 GS (out), 15 EO (out), 16 VCC (power) hidden to VCC
1 alternate drawing of the same symbol

## 74199
designator U?
8-Bit Shift Register
footprint DIP-24
simulation model 74199 (SIMCODE)
pins: 1 ~{K} (in), 2 J (in), 3 A (in), 4 QA (out), 5 B (in), 6 QB (out), 7 C (in), 8 QC (out), 9 D (in), 10 QD (out), 11 CK INH (in), 12 GND (power) hidden to GND, 13 CLK (in), 14 ~{CLR} (in), 15 QE (out), 16 E (in), 17 QF (out), 18 F (in), 19 QG (out), 20 G (in), 21 QH (out), 22 H (in), 23 SH/~{LD} (in), 24 VCC (power) hidden to VCC
1 alternate drawing of the same symbol

## SN74HC00
designator U?
Quad 2-IN Pos Nand G
footprint SO14
footprint DIP-14
part A pins: 1 (in), 2 (in), 3 (out), 7 GND (power) hidden to GND, 14 VCC (power) hidden to VCC
part B pins: 4 (in), 5 (in), 6 (out), 7 GND (power) hidden to GND, 14 VCC (power) hidden to VCC
part C pins: 7 GND (power) hidden to GND, 8 (out), 9 (in), 10 (in), 14 VCC (power) hidden to VCC
part D pins: 7 GND (power) hidden to GND, 11 (out), 12 (in), 13 (in), 14 VCC (power) hidden to VCC
2 alternate drawings of the same symbol

## SN74HC01
designator U?
Quad 2-IN Pos Nand G OCO
footprint SO14
footprint DIP-14
part A pins: 1 (oc), 2 (in), 3 (in), 7 GND (power) hidden to GND, 14 VCC (power) hidden to VCC
part B pins: 4 (oc), 5 (in), 6 (in), 7 GND (power) hidden to GND, 14 VCC (power) hidden to VCC
part C pins: 7 GND (power) hidden to GND, 8 (in), 9 (in), 10 (oc), 14 VCC (power) hidden to VCC
part D pins: 7 GND (power) hidden to GND, 11 (in), 12 (in), 13 (oc), 14 VCC (power) hidden to VCC
2 alternate drawings of the same symbol

## SN74HC02
designator U?
Quad 2-IN Pos Nor G
footprint SO14
footprint DIP-14
part A pins: 1 (out), 2 (in), 3 (in), 7 GND (power) hidden to GND, 14 VCC (power) hidden to VCC
part B pins: 4 (out), 5 (in), 6 (in), 7 GND (power) hidden to GND, 14 VCC (power) hidden to VCC
part C pins: 7 GND (power) hidden to GND, 8 (in), 9 (in), 10 (out), 14 VCC (power) hidden to VCC
part D pins: 7 GND (power) hidden to GND, 11 (in), 12 (in), 13 (out), 14 VCC (power) hidden to VCC
2 alternate drawings of the same symbol

## SN74HC03
designator U?
Quad 2-IN Pos Nand G OCO
footprint SO14
footprint DIP-14
part A pins: 1 (in), 2 (in), 3 (oc), 7 GND (power) hidden to GND, 14 VCC (power) hidden to VCC
part B pins: 4 (in), 5 (in), 6 (oc), 7 GND (power) hidden to GND, 14 VCC (power) hidden to VCC
part C pins: 7 GND (power) hidden to GND, 8 (oc), 9 (in), 10 (in), 14 VCC (power) hidden to VCC
part D pins: 7 GND (power) hidden to GND, 11 (oc), 12 (in), 13 (in), 14 VCC (power) hidden to VCC
2 alternate drawings of the same symbol

## SN74HC04
designator U?
Hex Inverters
footprint SO14
footprint DIP-14
part A pins: 1 (in), 2 (out), 7 GND (power) hidden to GND, 14 VCC (power) hidden to VCC
part B pins: 3 (in), 4 (out), 7 GND (power) hidden to GND, 14 VCC (power) hidden to VCC
part C pins: 5 (in), 6 (out), 7 GND (power) hidden to GND, 14 VCC (power) hidden to VCC
part D pins: 7 GND (power) hidden to GND, 8 (out), 9 (in), 14 VCC (power) hidden to VCC
part E pins: 7 GND (power) hidden to GND, 10 (out), 11 (in), 14 VCC (power) hidden to VCC
part F pins: 7 GND (power) hidden to GND, 12 (out), 13 (in), 14 VCC (power) hidden to VCC
2 alternate drawings of the same symbol

## SN74HC05
designator U?
Hex Inverters OCO
footprint SO14
footprint DIP-14
part A pins: 1 (in), 2 (oc), 7 GND (power) hidden to GND, 14 VCC (power) hidden to VCC
part B pins: 3 (in), 4 (oc), 7 GND (power) hidden to GND, 14 VCC (power) hidden to VCC
part C pins: 5 (in), 6 (oc), 7 GND (power) hidden to GND, 14 VCC (power) hidden to VCC
part D pins: 7 GND (power) hidden to GND, 8 (oc), 9 (in), 14 VCC (power) hidden to VCC
part E pins: 7 GND (power) hidden to GND, 10 (oc), 11 (in), 14 VCC (power) hidden to VCC
part F pins: 7 GND (power) hidden to GND, 12 (oc), 13 (in), 14 VCC (power) hidden to VCC
2 alternate drawings of the same symbol

## SN74HC08
designator U?
Quad 2-IN Pos And G
footprint SO14
footprint DIP-14
part A pins: 1 (in), 2 (in), 3 (out), 7 GND (power) hidden to GND, 14 VCC (power) hidden to VCC
part B pins: 4 (in), 5 (in), 6 (out), 7 GND (power) hidden to GND, 14 VCC (power) hidden to VCC
part C pins: 7 GND (power) hidden to GND, 8 (out), 9 (in), 10 (in), 14 VCC (power) hidden to VCC
part D pins: 7 GND (power) hidden to GND, 11 (out), 12 (in), 13 (in), 14 VCC (power) hidden to VCC
2 alternate drawings of the same symbol

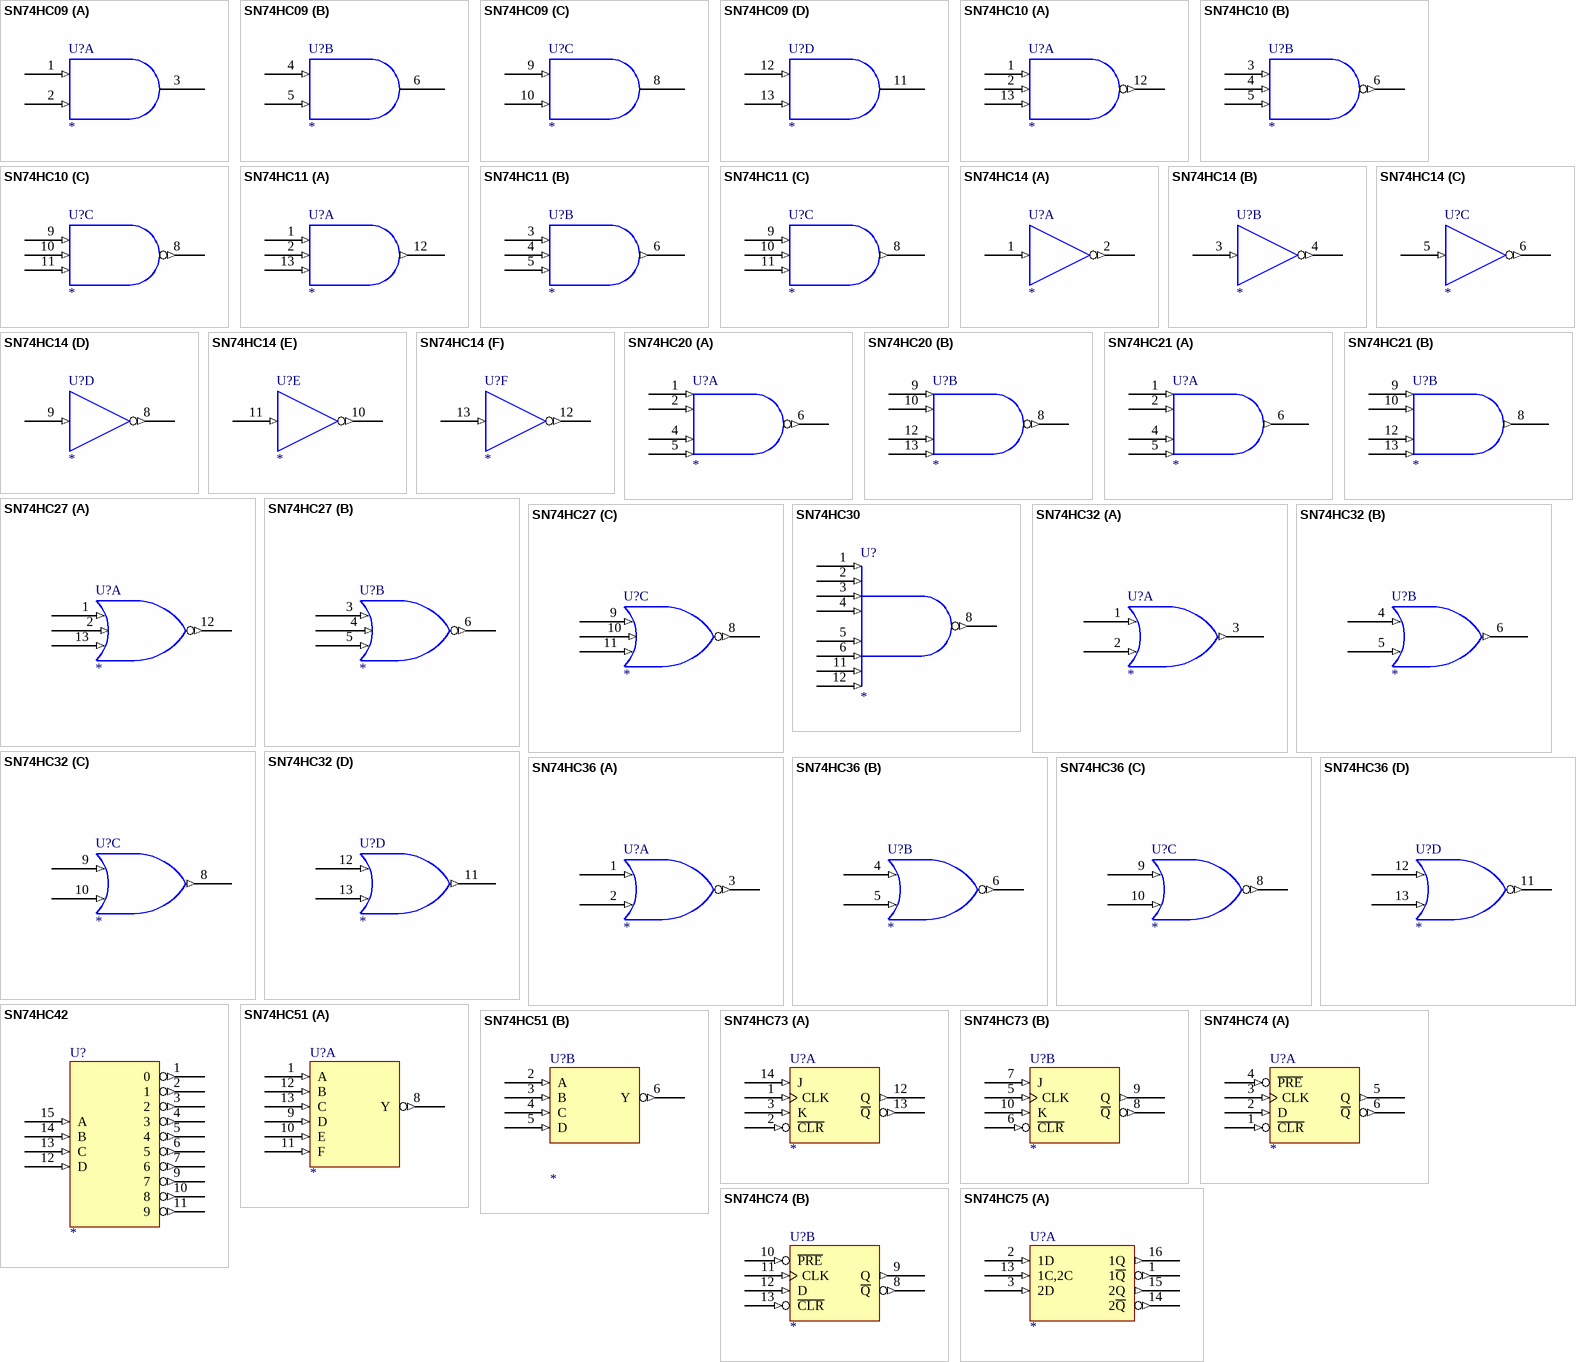
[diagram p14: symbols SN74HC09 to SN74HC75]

## SN74HC09
designator U?
Quad 2-IN Pos And G OCO
footprint SO14
footprint DIP-14
part A pins: 1 (in), 2 (in), 3 (oc), 7 GND (power) hidden to GND, 14 VCC (power) hidden to VCC
part B pins: 4 (in), 5 (in), 6 (oc), 7 GND (power) hidden to GND, 14 VCC (power) hidden to VCC
part C pins: 7 GND (power) hidden to GND, 8 (oc), 9 (in), 10 (in), 14 VCC (power) hidden to VCC
part D pins: 7 GND (power) hidden to GND, 11 (oc), 12 (in), 13 (in), 14 VCC (power) hidden to VCC
2 alternate drawings of the same symbol

## SN74HC10
designator U?
Triple 3-IN Pos Nand G
footprint SO14
footprint DIP-14
part A pins: 1 (in), 2 (in), 7 GND (power) hidden to GND, 12 (out), 13 (in), 14 VCC (power) hidden to VCC
part B pins: 3 (in), 4 (in), 5 (in), 6 (out), 7 GND (power) hidden to GND, 14 VCC (power) hidden to VCC
part C pins: 7 GND (power) hidden to GND, 8 (out), 9 (in), 10 (in), 11 (in), 14 VCC (power) hidden to VCC
2 alternate drawings of the same symbol

## SN74HC11
designator U?
Triple 3-IN Pos And G
footprint SO14
footprint DIP-14
part A pins: 1 (in), 2 (in), 7 GND (power) hidden to GND, 12 (out), 13 (in), 14 VCC (power) hidden to VCC
part B pins: 3 (in), 4 (in), 5 (in), 6 (out), 7 GND (power) hidden to GND, 14 VCC (power) hidden to VCC
part C pins: 7 GND (power) hidden to GND, 8 (out), 9 (in), 10 (in), 11 (in), 14 VCC (power) hidden to VCC
2 alternate drawings of the same symbol

## SN74HC14
designator U?
Hex Inverter SCH
footprint SO14
footprint DIP-14
part A pins: 1 (in), 2 (out), 7 GND (power) hidden to GND, 14 VCC (power) hidden to VCC
part B pins: 3 (in), 4 (out), 7 GND (power) hidden to GND, 14 VCC (power) hidden to VCC
part C pins: 5 (in), 6 (out), 7 GND (power) hidden to GND, 14 VCC (power) hidden to VCC
part D pins: 7 GND (power) hidden to GND, 8 (out), 9 (in), 14 VCC (power) hidden to VCC
part E pins: 7 GND (power) hidden to GND, 10 (out), 11 (in), 14 VCC (power) hidden to VCC
part F pins: 7 GND (power) hidden to GND, 12 (out), 13 (in), 14 VCC (power) hidden to VCC
2 alternate drawings of the same symbol

## SN74HC20
designator U?
Dual 4-IN Pos Nand G
footprint SO14
footprint DIP-14
part A pins: 1 (in), 2 (in), 4 (in), 5 (in), 6 (out), 7 GND (power) hidden to GND, 14 VCC (power) hidden to VCC
part B pins: 7 GND (power) hidden to GND, 8 (out), 9 (in), 10 (in), 12 (in), 13 (in), 14 VCC (power) hidden to VCC
2 alternate drawings of the same symbol

## SN74HC21
designator U?
Dual 4-IN Pos And G
footprint SO14
footprint DIP-14
part A pins: 1 (in), 2 (in), 4 (in), 5 (in), 6 (out), 7 GND (power) hidden to GND, 14 VCC (power) hidden to VCC
part B pins: 7 GND (power) hidden to GND, 8 (out), 9 (in), 10 (in), 12 (in), 13 (in), 14 VCC (power) hidden to VCC
2 alternate drawings of the same symbol

## SN74HC27
designator U?
Triple 3-IN Pos Nor G
footprint SO14
footprint DIP-14
part A pins: 1 (in), 2 (in), 7 GND (power) hidden to GND, 12 (out), 13 (in), 14 VCC (power) hidden to VCC
part B pins: 3 (in), 4 (in), 5 (in), 6 (out), 7 GND (power) hidden to GND, 14 VCC (power) hidden to VCC
part C pins: 7 GND (power) hidden to GND, 8 (out), 9 (in), 10 (in), 11 (in), 14 VCC (power) hidden to VCC
2 alternate drawings of the same symbol

## SN74HC30
designator U?
8-IN Nand Pos G
footprint SO14
footprint DIP-14
pins: 1 (in), 2 (in), 3 (in), 4 (in), 5 (in), 6 (in), 7 GND (power) hidden to GND, 8 (out), 11 (in), 12 (in), 14 VCC (power) hidden to VCC
2 alternate drawings of the same symbol

## SN74HC32
designator U?
Quad 2-IN Pos Or G
footprint SO14
footprint DIP-14
part A pins: 1 (in), 2 (in), 3 (out), 7 GND (power) hidden to GND, 14 VCC (power) hidden to VCC
part B pins: 4 (in), 5 (in), 6 (out), 7 GND (power) hidden to GND, 14 VCC (power) hidden to VCC
part C pins: 7 GND (power) hidden to GND, 8 (out), 9 (in), 10 (in), 14 VCC (power) hidden to VCC
part D pins: 7 GND (power) hidden to GND, 11 (out), 12 (in), 13 (in), 14 VCC (power) hidden to VCC
2 alternate drawings of the same symbol

## SN74HC36
designator U?
Quad 2-IN Pos NOR G
footprint SO14
footprint DIP-14
part A pins: 1 (in), 2 (in), 3 (out), 7 GND (power) hidden to GND, 14 VCC (power) hidden to VCC
part B pins: 4 (in), 5 (in), 6 (out), 7 GND (power) hidden to GND, 14 VCC (power) hidden to VCC
part C pins: 7 GND (power) hidden to GND, 8 (out), 9 (in), 10 (in), 14 VCC (power) hidden to VCC
part D pins: 7 GND (power) hidden to GND, 11 (out), 12 (in), 13 (in), 14 VCC (power) hidden to VCC
2 alternate drawings of the same symbol

## SN74HC42
designator U?
4-line BCD to 10-line decimal Dec
footprint SO16
footprint DIP-16
pins: 1 0 (out), 2 1 (out), 3 2 (out), 4 3 (out), 5 4 (out), 6 5 (out), 7 6 (out), 8 GND (power) hidden to GND, 9 7 (out), 10 8 (out), 11 9 (out), 12 D (in), 13 C (in), 14 B (in), 15 A (in), 16 VCC (power) hidden to VCC
1 alternate drawing of the same symbol

## SN74HC51
designator U?
DUAL 2-WIDE 2&3-IN AND-OR-INVERT G
footprint SO14
footprint DIP-14
part A pins: 1 A (in), 7 GND (power) hidden to GND, 8 Y (out), 9 D (in), 10 E (in), 11 F (in), 12 B (in), 13 C (in), 14 VCC (power) hidden to VCC
part B pins: 2 A (in), 3 B (in), 4 C (in), 5 D (in), 6 Y (out), 7 GND (power) hidden to GND, 14 VCC (power) hidden to VCC
1 alternate drawing of the same symbol

## SN74HC73
designator U?
DUAL J-K FF CR
footprint SO14
footprint DIP-14
part A pins: 1 CLK (in), 2 ~{CLR} (in), 3 K (in), 4 GND (power) hidden to GND, 11 VCC (power) hidden to VCC, 12 Q (out), 13 ~{Q} (out), 14 J (in)
part B pins: 4 GND (power) hidden to GND, 5 CLK (in), 6 ~{CLR} (in), 7 J (in), 8 ~{Q} (out), 9 Q (out), 10 K (in), 11 VCC (power) hidden to VCC
1 alternate drawing of the same symbol

## SN74HC74
designator U?
DUAL D PET FF RS CR
footprint SO14
footprint DIP-14
part A pins: 1 ~{CLR} (in), 2 D (in), 3 CLK (in), 4 ~{PRE} (in), 5 Q (out), 6 ~{Q} (out), 7 GND (power) hidden to GND, 14 VCC (power) hidden to VCC
part B pins: 7 GND (power) hidden to GND, 8 ~{Q} (out), 9 Q (out), 10 ~{PRE} (in), 11 CLK (in), 12 D (in), 13 ~{CLR} (in), 14 VCC (power) hidden to VCC
1 alternate drawing of the same symbol

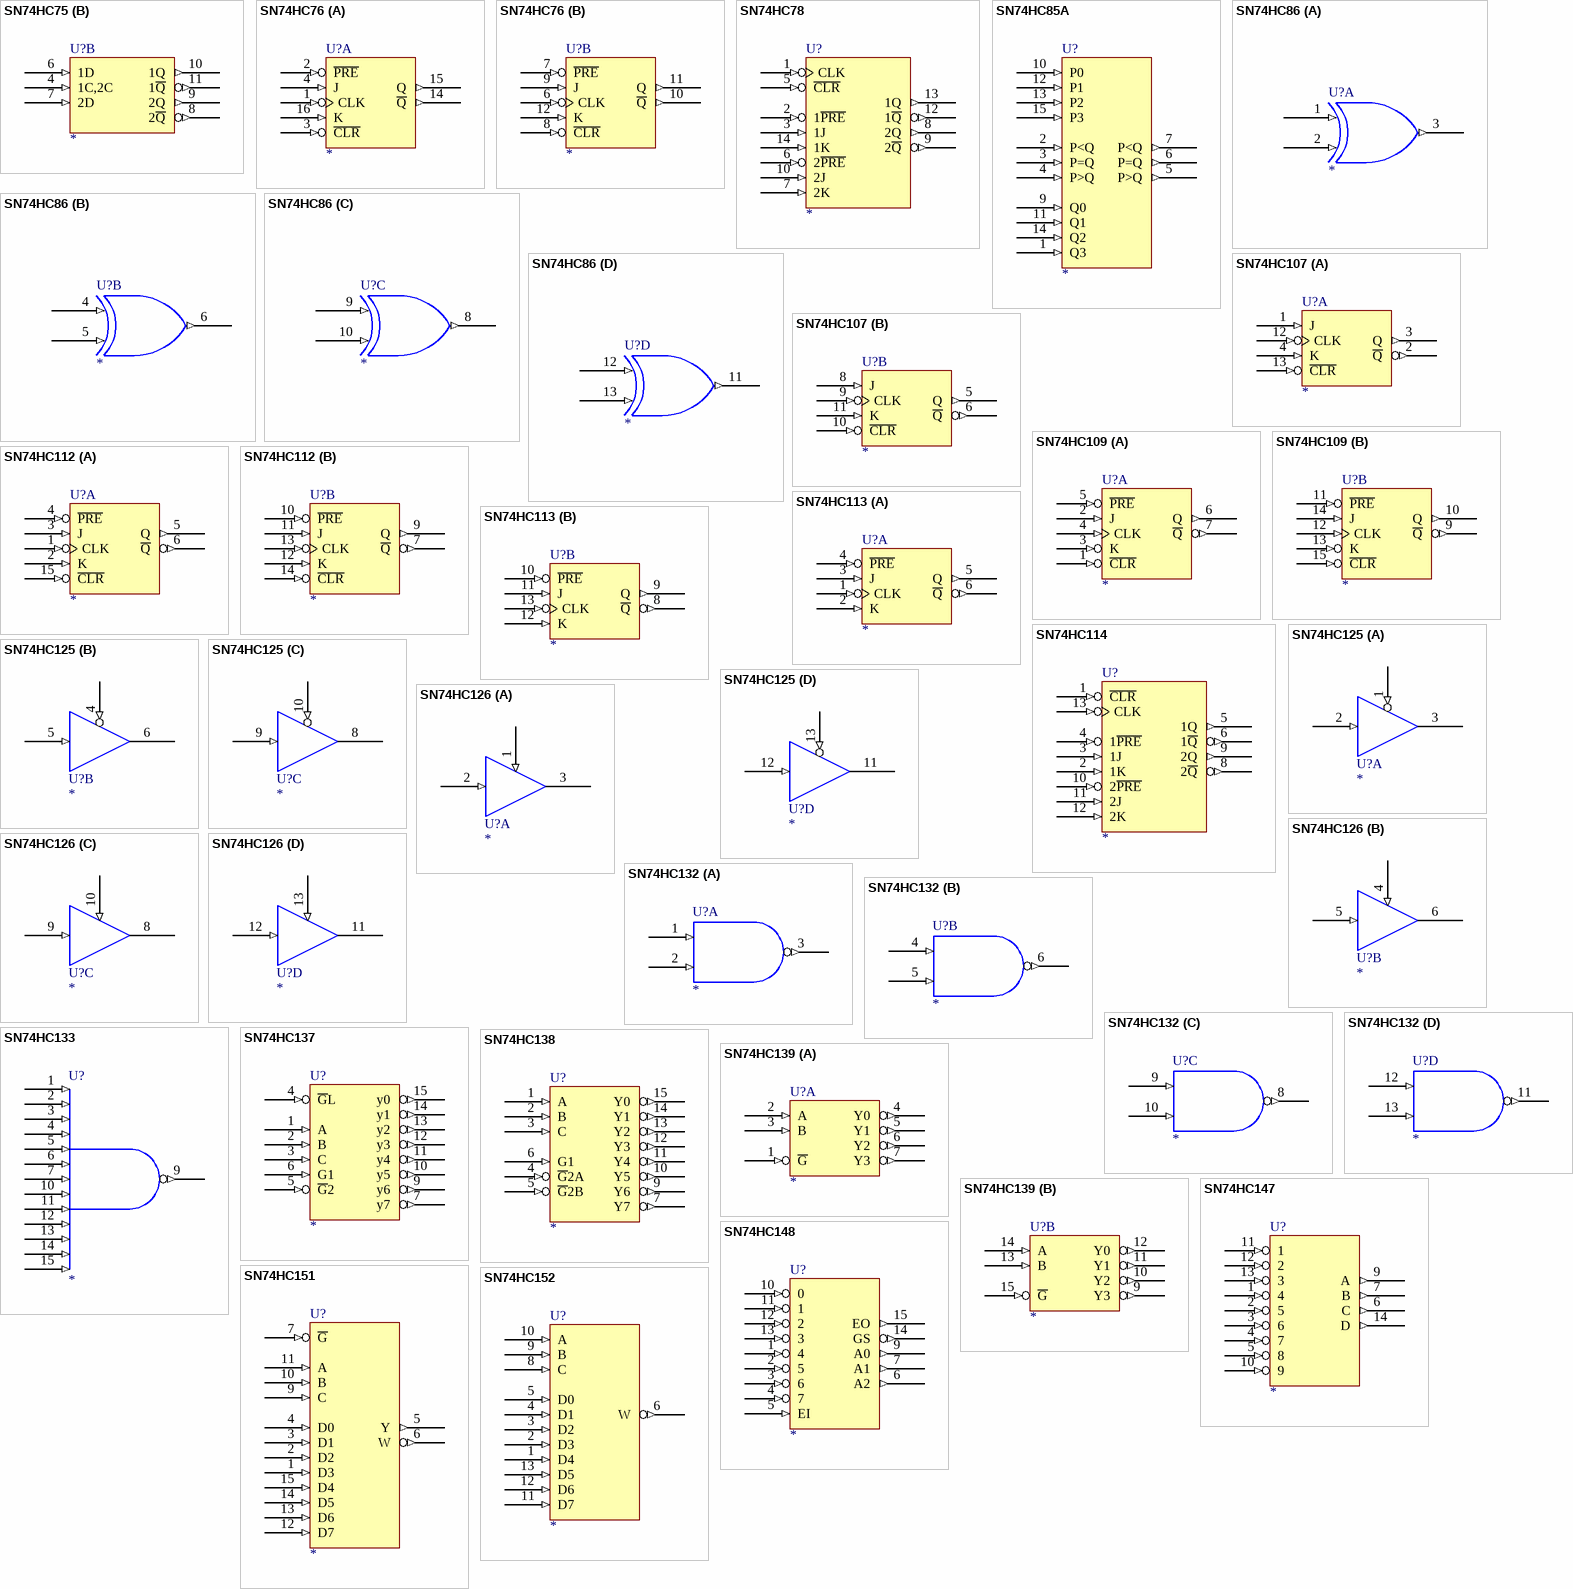
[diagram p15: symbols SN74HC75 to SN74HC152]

## SN74HC75
designator U?
4-BIT BISTABLE LCH
footprint SO16
footprint DIP-16
part A pins: 1 1~{Q} (out), 2 1D (in), 3 2D (in), 5 VCC (power) hidden to VCC, 12 GND (power) hidden to GND, 13 1C,2C (in), 14 2~{Q} (out), 15 2Q (out), 16 1Q (out)
part B pins: 4 1C,2C (in), 5 VCC (power) hidden to VCC, 6 1D (in), 7 2D (in), 8 2~{Q} (out), 9 2Q (out), 10 1Q (out), 11 1~{Q} (out), 12 GND (power) hidden to GND
1 alternate drawing of the same symbol

## SN74HC76
designator U?
DUAL J-K NET FF RS CR
footprint SO16
footprint DIP-16
part A pins: 1 CLK (in), 2 ~{PRE} (in), 3 ~{CLR} (in), 4 J (in), 5 VCC (power) hidden to VCC, 13 GND (power) hidden to GND, 14 ~{Q} (out), 15 Q (out), 16 K (in)
part B pins: 5 VCC (power) hidden to VCC, 6 CLK (in), 7 ~{PRE} (in), 8 ~{CLR} (in), 9 J (in), 10 ~{Q} (out), 11 Q (out), 12 K (in), 13 GND (power) hidden to GND
1 alternate drawing of the same symbol

## SN74HC78
designator U?
DUAL J-K FF RS COM CLK COM CR
footprint SO14
footprint DIP-14
pins: 1 CLK (in), 2 1~{PRE} (in), 3 1J (in), 4 VCC (power) hidden to VCC, 5 ~{CLR} (in), 6 2~{PRE} (in), 7 2K (in), 8 2Q (out), 9 2~{Q} (out), 10 2J (in), 11 GND (power) hidden to GND, 12 1~{Q} (out), 13 1Q (out), 14 1K (in)
1 alternate drawing of the same symbol

## SN74HC85A
designator U?
4-BIT MAGNITUDE COMP
footprint DIP-16
pins: 1 Q3 (in), 2 P<Q (in), 3 P=Q (in), 4 P>Q (in), 5 P>Q (out), 6 P=Q (out), 7 P<Q (out), 8 GND (power) hidden to GND, 9 Q0 (in), 10 P0 (in), 11 Q1 (in), 12 P1 (in), 13 P2 (in), 14 Q2 (in), 15 P3 (in), 16 VCC (power) hidden to VCC
1 alternate drawing of the same symbol

## SN74HC86
designator U?
QUAD 2-IN XOR  G
footprint SO14
footprint DIP-14
part A pins: 1 (in), 2 (in), 3 (out), 7 GND (power) hidden to GND, 14 VCC (power) hidden to VCC
part B pins: 4 (in), 5 (in), 6 (out), 7 GND (power) hidden to GND, 14 VCC (power) hidden to VCC
part C pins: 7 GND (power) hidden to GND, 8 (out), 9 (in), 10 (in), 14 VCC (power) hidden to VCC
part D pins: 7 GND (power) hidden to GND, 11 (out), 12 (in), 13 (in), 14 VCC (power) hidden to VCC
1 alternate drawing of the same symbol

## SN74HC107
designator U?
DUAL J-K FF CR
footprint SO14
footprint DIP-14
part A pins: 1 J (in), 2 ~{Q} (out), 3 Q (out), 4 K (in), 7 GND (power) hidden to GND, 12 CLK (in), 13 ~{CLR} (in), 14 VCC (power) hidden to VCC
part B pins: 5 Q (out), 6 ~{Q} (out), 7 GND (power) hidden to GND, 8 J (in), 9 CLK (in), 10 ~{CLR} (in), 11 K (in), 14 VCC (power) hidden to VCC
1 alternate drawing of the same symbol

## SN74HC109
designator U?
DUAL J-K PET FF RS CR
footprint SO16
footprint DIP-16
part A pins: 1 ~{CLR} (in), 2 J (in), 3 K (in), 4 CLK (in), 5 ~{PRE} (in), 6 Q (out), 7 ~{Q} (out), 8 GND (power) hidden to GND, 16 VCC (power) hidden to VCC
part B pins: 8 GND (power) hidden to GND, 9 ~{Q} (out), 10 Q (out), 11 ~{PRE} (in), 12 CLK (in), 13 K (in), 14 J (in), 15 ~{CLR} (in), 16 VCC (power) hidden to VCC
1 alternate drawing of the same symbol

## SN74HC112
designator U?
DUAL J-K NET FF RS CR
footprint SO16
footprint DIP-16
part A pins: 1 CLK (in), 2 K (in), 3 J (in), 4 ~{PRE} (in), 5 Q (out), 6 ~{Q} (out), 8 GND (power) hidden to GND, 15 ~{CLR} (in), 16 VCC (power) hidden to VCC
part B pins: 7 ~{Q} (out), 8 GND (power) hidden to GND, 9 Q (out), 10 ~{PRE} (in), 11 J (in), 12 K (in), 13 CLK (in), 14 ~{CLR} (in), 16 VCC (power) hidden to VCC
1 alternate drawing of the same symbol

## SN74HC113
designator U?
DUAL J-K NET FF RS
footprint SO14
footprint DIP-14
part A pins: 1 CLK (in), 2 K (in), 3 J (in), 4 ~{PRE} (in), 5 Q (out), 6 ~{Q} (out), 7 GND (power) hidden to GND, 14 VCC (power) hidden to VCC
part B pins: 7 GND (power) hidden to GND, 8 ~{Q} (out), 9 Q (out), 10 ~{PRE} (in), 11 J (in), 12 K (in), 13 CLK (in), 14 VCC (power) hidden to VCC
1 alternate drawing of the same symbol

## SN74HC114
designator U?
DUAL J-K NET FF RS COM CR COM CLK
footprint SO14
footprint DIP-14
pins: 1 ~{CLR} (in), 2 1K (in), 3 1J (in), 4 1~{PRE} (in), 5 1Q (out), 6 1~{Q} (out), 7 GND (power) hidden to GND, 8 2~{Q} (out), 9 2Q (out), 10 2~{PRE} (in), 11 2J (in), 12 2K (in), 13 CLK (in), 14 VCC (power) hidden to VCC
1 alternate drawing of the same symbol

## SN74HC125
designator U?
QUAD BUS BUF 3SO
footprint DIP-14
part A pins: 1 (in), 2 (in), 3 (hiz), 7 GND (power) hidden to GND, 14 VCC (power) hidden to VCC
part B pins: 4 (in), 5 (in), 6 (hiz), 7 GND (power) hidden to GND, 14 VCC (power) hidden to VCC
part C pins: 7 GND (power) hidden to GND, 8 (hiz), 9 (in), 10 (in), 14 VCC (power) hidden to VCC
part D pins: 7 GND (power) hidden to GND, 11 (hiz), 12 (in), 13 (in), 14 VCC (power) hidden to VCC
2 alternate drawings of the same symbol

## SN74HC126
designator U?
QUAD BUS BUF 3SO
footprint DIP-14
part A pins: 1 (in), 2 (in), 3 (hiz), 7 GND (power) hidden to GND, 14 VCC (power) hidden to VCC
part B pins: 4 (in), 5 (in), 6 (hiz), 7 GND (power) hidden to GND, 14 VCC (power) hidden to VCC
part C pins: 7 GND (power) hidden to GND, 8 (hiz), 9 (in), 10 (in), 14 VCC (power) hidden to VCC
part D pins: 7 GND (power) hidden to GND, 11 (hiz), 12 (in), 13 (in), 14 VCC (power) hidden to VCC
2 alternate drawings of the same symbol

## SN74HC132
designator U?
QUAD 2-IN POS NAND SCH
footprint SO14
footprint DIP-14
part A pins: 1 (in), 2 (in), 3 (out), 7 GND (power) hidden to GND, 14 VCC (power) hidden to VCC
part B pins: 4 (in), 5 (in), 6 (out), 7 GND (power) hidden to GND, 14 VCC (power) hidden to VCC
part C pins: 7 GND (power) hidden to GND, 8 (out), 9 (in), 10 (in), 14 VCC (power) hidden to VCC
part D pins: 7 GND (power) hidden to GND, 11 (out), 12 (in), 13 (in), 14 VCC (power) hidden to VCC
2 alternate drawings of the same symbol

## SN74HC133
designator U?
13-IN POS Nand G
footprint SO16
footprint DIP-16
pins: 1 (in), 2 (in), 3 (in), 4 (in), 5 (in), 6 (in), 7 (in), 8 GND (power) hidden to GND, 9 (out), 10 (in), 11 (in), 12 (in), 13 (in), 14 (in), 15 (in), 16 VCC (power) hidden to VCC
2 alternate drawings of the same symbol

## SN74HC137
designator U?
3-8LINE DEC/DEMUL ADDRESS LCH
footprint SO16
footprint DIP-16
pins: 1 A (in), 2 B (in), 3 C (in), 4 ~{G}L (in), 5 ~{G}2 (in), 6 G1 (in), 7 y7 (out), 8 GND (power) hidden to GND, 9 y6 (out), 10 y5 (out), 11 y4 (out), 12 y3 (out), 13 y2 (out), 14 y1 (out), 15 y0 (out), 16 VCC (power) hidden to VCC
1 alternate drawing of the same symbol

## SN74HC138
designator U?
3-8LINE DEC/DEMUL
footprint SO16
footprint DIP-16
pins: 1 A (in), 2 B (in), 3 C (in), 4 ~{G}2A (in), 5 ~{G}2B (in), 6 G1 (in), 7 Y7 (out), 8 GND (power) hidden to GND, 9 Y6 (out), 10 Y5 (out), 11 Y4 (out), 12 Y3 (out), 13 Y2 (out), 14 Y1 (out), 15 Y0 (out), 16 VCC (power) hidden to VCC
1 alternate drawing of the same symbol

## SN74HC139
designator U?
DUAL 2-4LINE DEC/DEMULT
footprint SO16W
footprint DIP-16
part A pins: 1 ~{G} (in), 2 A (in), 3 B (in), 4 Y0 (out), 5 Y1 (out), 6 Y2 (out), 7 Y3 (out), 8 GND (power) hidden to GND, 16 VCC (power) hidden to VCC
part B pins: 8 GND (power) hidden to GND, 9 Y3 (out), 10 Y2 (out), 11 Y1 (out), 12 Y0 (out), 13 B (in), 14 A (in), 15 ~{G} (in), 16 VCC (power) hidden to VCC
1 alternate drawing of the same symbol

## SN74HC147
designator U?
10-4 LINE PRIORITY ENC
footprint DIP-16
pins: 1 4 (in), 2 5 (in), 3 6 (in), 4 7 (in), 5 8 (in), 6 C (out), 7 B (out), 8 GND (power) hidden to GND, 9 A (out), 10 9 (in), 11 1 (in), 12 2 (in), 13 3 (in), 14 D (out), 16 VCC (power) hidden to VCC
1 alternate drawing of the same symbol

## SN74HC148
designator U?
8-3 LINE PRIORITY ENC
footprint SO16W
footprint DIP-16
pins: 1 4 (in), 2 5 (in), 3 6 (in), 4 7 (in), 5 EI (in), 6 A2 (out), 7 A1 (out), 8 GND (power) hidden to GND, 9 A0 (out), 10 0 (in), 11 1 (in), 12 2 (in), 13 3 (in), 14 GS (out), 15 EO (out), 16 VCC (power) hidden to VCC
1 alternate drawing of the same symbol

## SN74HC151
designator U?
DATA SELEC/MUX
footprint SO16
footprint DIP-16
pins: 1 D3 (in), 2 D2 (in), 3 D1 (in), 4 D0 (in), 5 Y (out), 6 W (out), 7 ~{G} (in), 8 GND (power) hidden to GND, 9 C (in), 10 B (in), 11 A (in), 12 D7 (in), 13 D6 (in), 14 D5 (in), 15 D4 (in), 16 VCC (power) hidden to VCC
1 alternate drawing of the same symbol

## SN74HC152
designator U?
8 TO 1-LINE DATA SELEC/MUX
footprint SO14
footprint DIP-14
pins: 1 D4 (in), 2 D3 (in), 3 D2 (in), 4 D1 (in), 5 D0 (in), 6 W (out), 7 GND (power) hidden to GND, 8 C (in), 9 B (in), 10 A (in), 11 D7 (in), 12 D6 (in), 13 D5 (in), 14 VCC (power) hidden to VCC
1 alternate drawing of the same symbol

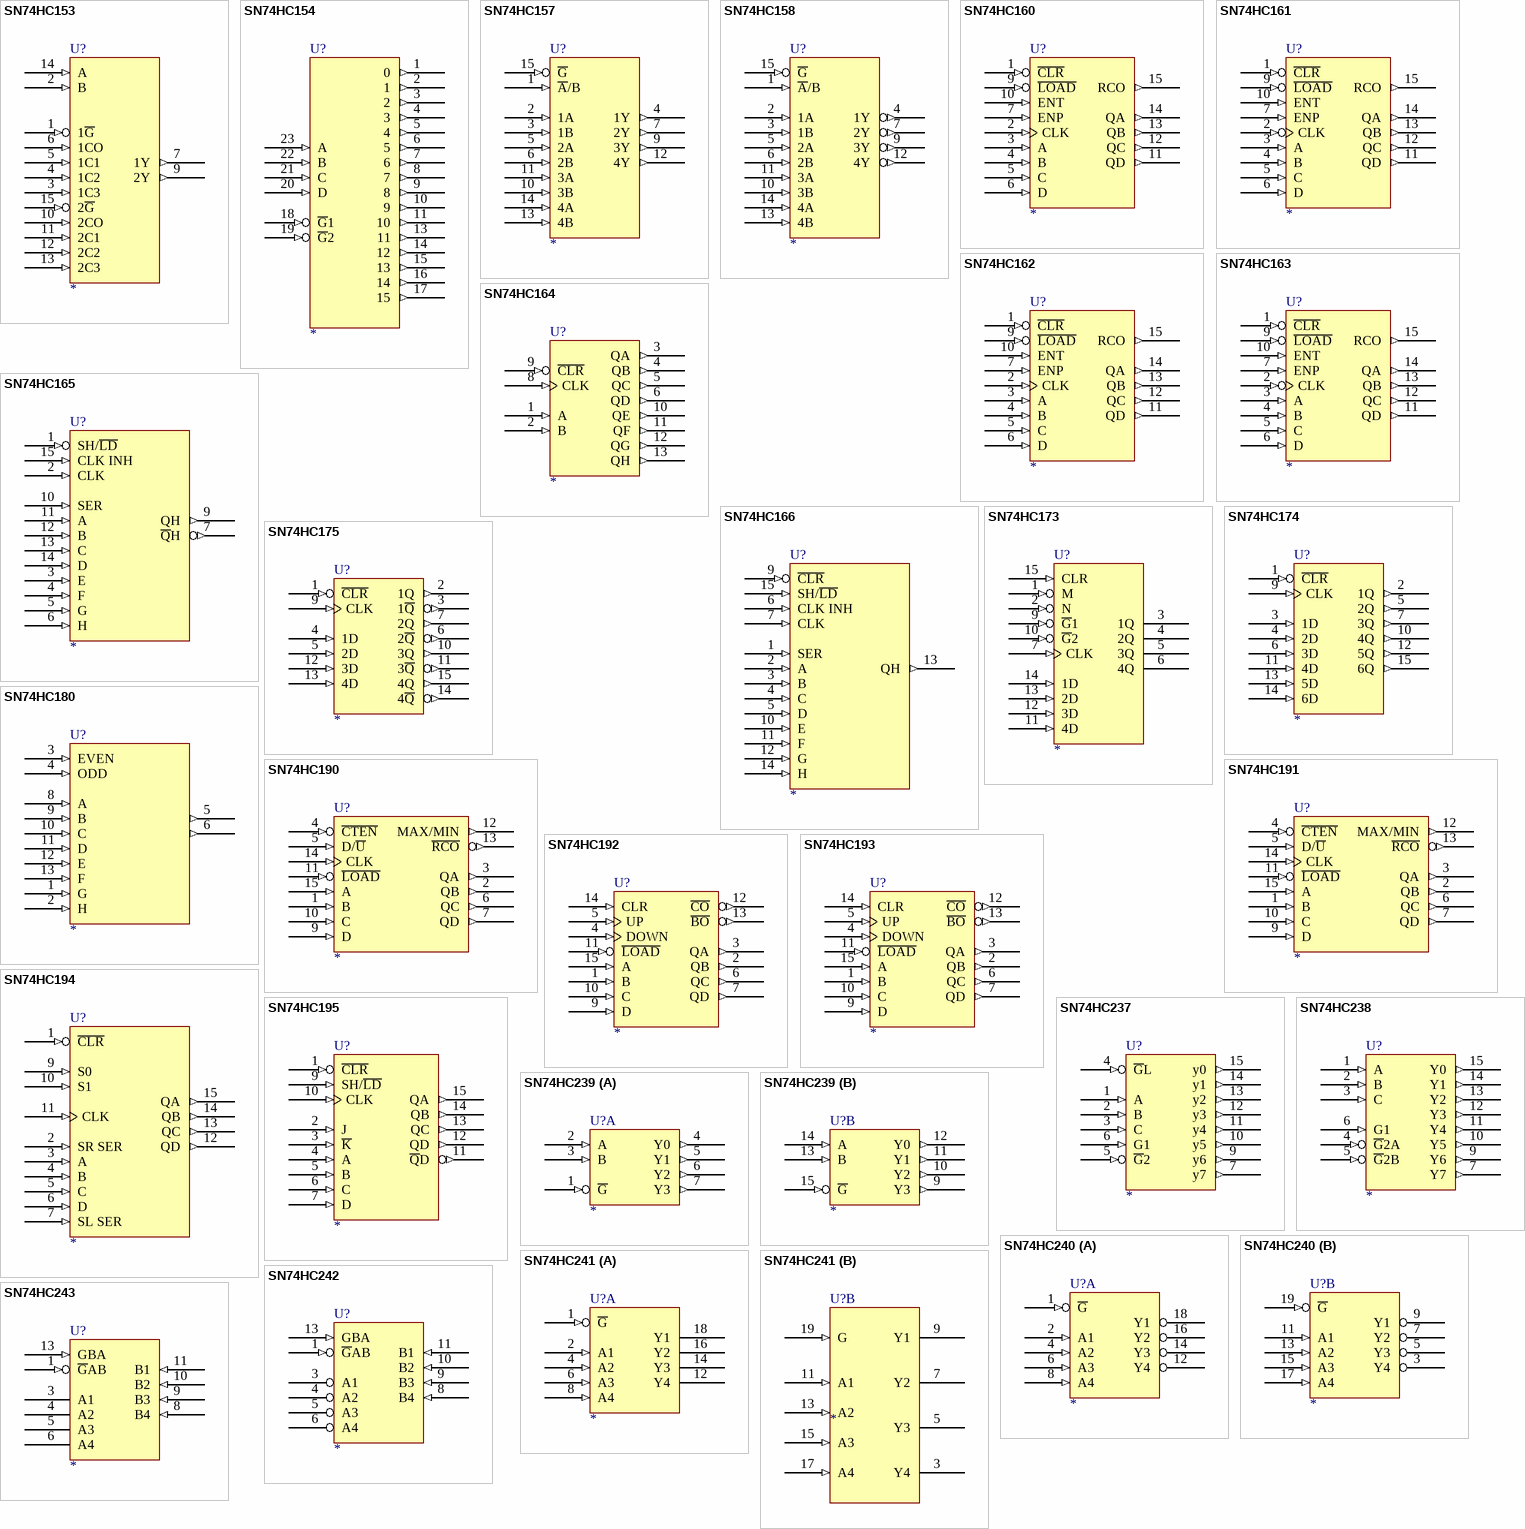
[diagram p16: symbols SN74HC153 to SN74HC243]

## SN74HC153
designator U?
DUAL 4-1 LINE DATA SELEC/MUX
footprint SO16
footprint SO16W
footprint DIP-16
pins: 1 1~{G} (in), 2 B (in), 3 1C3 (in), 4 1C2 (in), 5 1C1 (in), 6 1CO (in), 7 1Y (out), 8 GND (power) hidden to GND, 9 2Y (out), 10 2CO (in), 11 2C1 (in), 12 2C2 (in), 13 2C3 (in), 14 A (in), 15 2~{G} (in), 16 VCC (power) hidden to VCC
1 alternate drawing of the same symbol

## SN74HC154
designator U?
4-16LINE DEC DEMUL
footprint SO24W
footprint DIP-24
pins: 1 0 (out), 2 1 (out), 3 2 (out), 4 3 (out), 5 4 (out), 6 5 (out), 7 6 (out), 8 7 (out), 9 8 (out), 10 9 (out), 11 10 (out), 12 GND (power) hidden to GND, 13 11 (out), 14 12 (out), 15 13 (out), 16 14 (out), 17 15 (out), 18 ~{G}1 (in), 19 ~{G}2 (in), 20 D (in), 21 C (in), 22 B (in), 23 A (in), 24 VCC (power) hidden to VCC
1 alternate drawing of the same symbol

## SN74HC157
designator U?
QUAD 2-1LINE DATA SELEC/MUX
footprint SO16
footprint DIP-16
pins: 1 ~{A}/B (in), 2 1A (in), 3 1B (in), 4 1Y (out), 5 2A (in), 6 2B (in), 7 2Y (out), 8 GND (power) hidden to GND, 9 3Y (out), 10 3B (in), 11 3A (in), 12 4Y (out), 13 4B (in), 14 4A (in), 15 ~{G} (in), 16 VCC (power) hidden to VCC
1 alternate drawing of the same symbol

## SN74HC158
designator U?
QUAD 2-1LINE DATA SELEC/MUX
footprint SO16
footprint DIP-16
pins: 1 ~{A}/B (in), 2 1A (in), 3 1B (in), 4 1Y (out), 5 2A (in), 6 2B (in), 7 2Y (out), 8 GND (power) hidden to GND, 9 3Y (out), 10 3B (in), 11 3A (in), 12 4Y (out), 13 4B (in), 14 4A (in), 15 ~{G} (in), 16 VCC (power) hidden to VCC
1 alternate drawing of the same symbol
